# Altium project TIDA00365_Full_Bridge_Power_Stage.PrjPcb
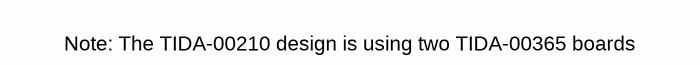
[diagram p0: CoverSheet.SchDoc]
CopyrightYear: 2016; EVM_Orderable: N/A; PCB_Layout: V.Pizzolante; PCB_Rev: E1; PRJ_Customer: Public Release; PRJ_Engineer: V.Pizzolante; PRJ_Number: TIDA-00365; PRJ_Title: Full_Bridge_Power_Stage; SCH_Rev: E1; TechSupport: http://www.ti.com/support; TID: TIDA-00365
6 sheets, 182 parts. Net scope: global (net labels, ports and power ports of the same name join across sheets).
Board file: TIDA00365.PcbDoc
Sheets:
  CoverSheet.SchDoc
  Protections.SchDoc
  Power Supply.SchDoc
  Full Bridge.SchDoc
  Interfaces.SchDoc
  TIDA00365_Screws.SchDoc

## Sheet CoverSheet.SchDoc
size 431 x 279 mm; Date: Not shown in title block; ApprovedBy: Not shown in title block; CheckedBy: Not shown in title block; Author: Not shown in title block; CompanyName: Not shown in title block; Engineer: Not shown in title block; Organization: Not shown in title block; Address1: Not shown in title block; Address2: Not shown in title block; Address3: Not shown in title block; Address4: Not shown in title block; DocumentNumber: 1; Revision: Use project parameter SCH_Rev; SheetNumber: 1; SheetTotal: 3

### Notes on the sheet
- Note: The TIDA-00210 design is using two TIDA-00365 boards

## Sheet Protections.SchDoc
size 431 x 279 mm; Date: Not shown in title block; ApprovedBy: Not shown in title block; CheckedBy: Not shown in title block; Author: Not shown in title block; CompanyName: Not shown in title block; Engineer: Not shown in title block; Organization: Not shown in title block; Address1: Not shown in title block; Address2: Not shown in title block; Address3: Not shown in title block; Address4: Not shown in title block; DocumentNumber: 1; Revision: Use project parameter SCH_Rev; SheetNumber: 2; SheetTotal: 3
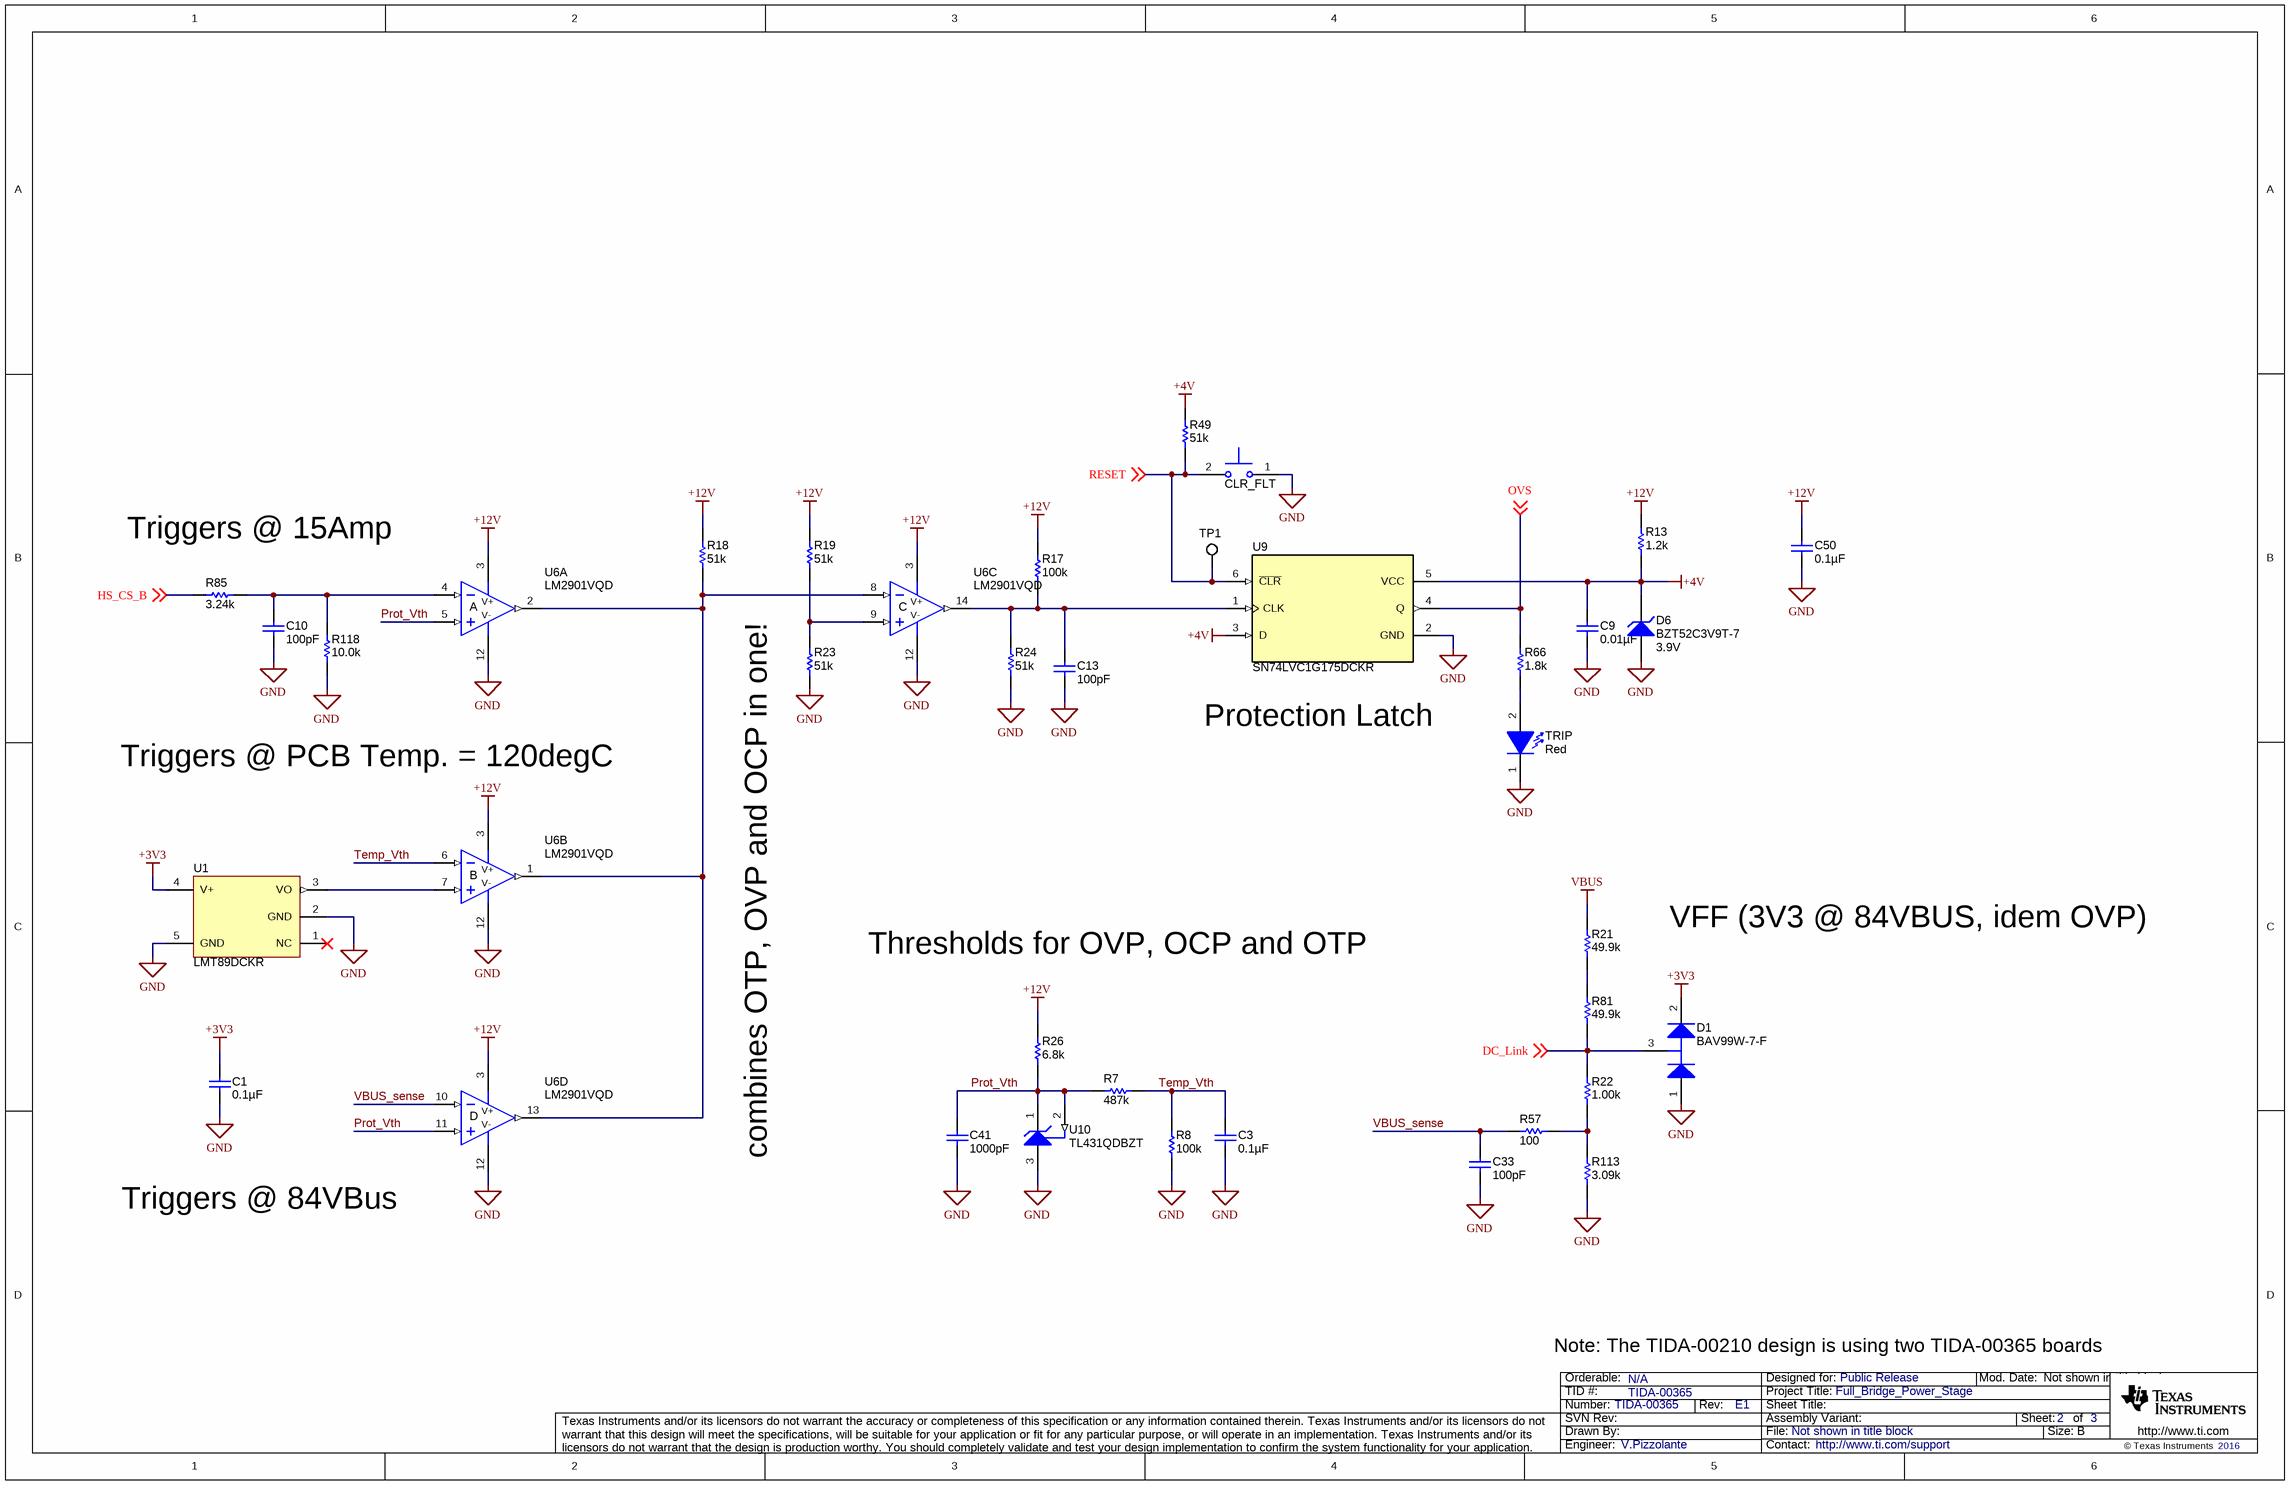
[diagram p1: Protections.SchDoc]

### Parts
C1  ValueDisplayed: 0.1µF  [0402]  (hidden comment: C1005X7R1E104M050BB)
C3  ValueDisplayed: 0.1µF  [0402]  (hidden comment: 885012105016)
C9  ValueDisplayed: 0.01µF  [0402]  (hidden comment: 885012205031)
C10  ValueDisplayed: 100pF  [0402]  (hidden comment: CC0402KRX7R9BB101)
C13  ValueDisplayed: 100pF  [0402]  (hidden comment: CC0402KRX7R9BB101)
C33  ValueDisplayed: 100pF  [0402]  (hidden comment: CC0402KRX7R9BB101)
C41  ValueDisplayed: 1000pF  [0402]  (hidden comment: 885012205044)
C50  ValueDisplayed: 0.1µF  [0402]  (hidden comment: C1005X7R1E104M050BB)
CLR_FLT  TL1015AF160QG  [SW_TL1015AF160QG]  (value not drawn)
D1  BAV99W-7-F  [SOT-323]
D6  BZT52C3V9T-7  value 3.9V  [SOD-523]
R7  ValueDisplayed: 487k  [0402]  (hidden comment: CRCW0402487KFKED)
R8  ValueDisplayed: 100k  [0402]  (hidden comment: CRCW0402100KFKED)
R13  ValueDisplayed: 1.2k  [0402]  (hidden comment: CRCW04021K20JNED)
R17  ValueDisplayed: 100k  [0402]  (hidden comment: CRCW0402100KJNED)
R18  ValueDisplayed: 51k  [0402]  (hidden comment: CRCW040251K0JNED)
R19  ValueDisplayed: 51k  [0402]  (hidden comment: CRCW040251K0JNED)
R21  ValueDisplayed: 49.9k  [0402]  (hidden comment: CRCW040249K9FKED)
R22  ValueDisplayed: 1.00k  [0402]  (hidden comment: CRCW04021K00FKED)
R23  ValueDisplayed: 51k  [0402]  (hidden comment: CRCW040251K0JNED)
R24  ValueDisplayed: 51k  [0402]  (hidden comment: CRCW040251K0JNED)
R26  ValueDisplayed: 6.8k  [0402]  (hidden comment: CRCW04026K80JNED)
R49  ValueDisplayed: 51k  [0402]  (hidden comment: CRCW040251K0JNED)
R57  ValueDisplayed: 100  [0402]  (hidden comment: CRCW0402100RJNED)
R66  ValueDisplayed: 1.8k  [0402]  (hidden comment: CRCW04021K80JNED)
R81  ValueDisplayed: 49.9k  [0402]  (hidden comment: CRCW040249K9FKED)
R85  ValueDisplayed: 3.24k  [0402]  (hidden comment: CRCW04023K24FKED)
R113  ValueDisplayed: 3.09k  [0402]  (hidden comment: CRCW04023K09FKED)
R118  ValueDisplayed: 10.0k  [0402]  (hidden comment: CRCW040210K0FKED)
TP1  5002  [Keystone5002]  (value not drawn)
TRIP  value Red  [WL-SMCW_RED]  (hidden comment: 150060RS75000)
U1  LMT89DCKR  [DCK0005A_N]
U6  LM2901VQD  [D0014A_N]  (parts A,B,C,D of 4)
U9  SN74LVC1G175DCKR  [DCK0006A_N]
U10  TL431QDBZT  [DBZ0003A_N]

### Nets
+3V3: C1.1 D1.2(K) U1.4(V+)
+4V: C9.1 D6.1(K) R13.1 R49.2 U9.3(D) U9.5(VCC)
+12V: C50.1 R13.2 R17.2 R18.1 R19.1 R26.2 U6.3(V+)
GND: C1.2 C3.2 C9.2 C10.2 C13.2 C33.2 C41.2 C50.2 CLR_FLT.1 D1.1(A) D6.2(A) R8.1 R23.2 R24.1 R113.1 R118.1 TRIP.1(K) U1.2(GND) U1.5(GND) U6.12(V-) U9.2(GND) U10.3(ANODE)
VBUS: R21.2
DC_Link: D1.3(C) R22.2 R81.1 ; off-sheet DC_Link
HS_CS_B: R85.1 ; off-sheet HS_CS_B  [project net BOUT_2]
OVS: R66.1 U9.4(Q) ; off-sheet OVS
Prot_Vth: C41.1 R7.2 R26.1 U6.5(+IN1) U6.11(+IN4) U10.1(CATHODE) U10.2(REF)
RESET: CLR_FLT.2 R49.1 TP1.1 U9.6(~{CLR}) ; off-sheet RESET
Temp_Vth: C3.1 R7.1 R8.2 U6.6(-IN2)
VBUS_sense: C33.1 R57.1 U6.10(-IN4)
NetC10_1: C10.1 R85.2 R118.2 U6.4(-IN1)
NetC13_1: C13.1 R17.1 R24.2 U6.14(OUT3) U9.1(CLK)
NetR18_2: R18.2 U6.1(OUT2) U6.2(OUT1) U6.8(-IN3) U6.13(OUT4)
NetR19_2: R19.2 R23.1 U6.9(+IN3)
NetR21_1: R21.1 R81.2
NetR22_1: R22.1 R57.2 R113.2
NetR66_2: R66.2 TRIP.2(A)
NetU1_3: U1.3(VO) U6.7(+IN2)

Not connected (* = marked no-connect by the designer): U1 1(NC)*

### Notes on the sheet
- Triggers @ 15Amp
- Triggers @ PCB Temp. = 120degC
- Protection Latch
- (near R23) combines OTP, OVP and OCP in one!
- Thresholds for OVP, OCP and OTP
- VFF (3V3 @ 84VBUS, idem OVP)
- Triggers @ 84VBus
- Note: The TIDA-00210 design is using two TIDA-00365 boards

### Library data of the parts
C1 C50 = C1005X7R1E104M050BB: CAP, CERM, 0.1 µF, 25 V, +/- 20%, X7R, 0402; Manufacturer: TDK; Polarized: N; CompType: Capacitor; Value: 0.1uF; U/M: EA; Cap_F: 0.0000001; Tolerance_%: 20; Value1: Unknown; VDC_V: 25; Value2: 25V; TaMin_C: -55; TaMax_C: 125; AEC Category: Q200
C3 = 885012105016: CAP, CERM, 0.1 µF, 16 V, +/- 20%, X5R, 0402; Manufacturer: Wurth Elektronik; Polarized: N; CompType: Capacitor; Value: 0.1uF; U/M: EA; Cap_F: 0.0000001; Tolerance_%: 20; Value1: Unknown; VDC_V: 16; Value2: 16V; TaMin_C: -55; TaMax_C: 85; AEC Category: Q200
C9 = 885012205031: CAP, CERM, 0.01 µF, 16 V, +/- 10%, X7R, 0402; Manufacturer: Wurth Elektronik; Polarized: N; CompType: Capacitor; Value: 0.01uF; U/M: EA; Cap_F: 0.00000001; Tolerance_%: 10; Value1: Unknown; VDC_V: 16; Value2: 16V; TaMin_C: -55; TaMax_C: 125; AEC Category: Q200
C10 C13 C33 = CC0402KRX7R9BB101: CAP, CERM, 100 pF, 50 V, +/- 10%, X7R, 0402; Manufacturer: Yageo America; Polarized: N; CompType: Capacitor; Value: 100pF; U/M: EA; Cap_F: 0.0000000001; Tolerance_%: 10; Value1: Unknown; VDC_V: 50; Value2: 50V; TaMin_C: -55; TaMax_C: 125; AEC Category: Q200
C41 = 885012205044: CAP, CERM, 1000 pF, 25 V, +/- 10%, X7R, 0402; Manufacturer: Wurth Elektronik; Polarized: N; CompType: Capacitor; Value: 1000pF; U/M: EA; Cap_F: 0.000000001; Tolerance_%: 10; Value1: Unknown; VDC_V: 25; Value2: 25V; TaMin_C: -55; TaMax_C: 125; AEC Category: Q200
CLR_FLT = TL1015AF160QG: Switch, Tactile, SPST-NO, 0.05A, 12V, SMT; Manufacturer: E-Switch; SymbolCreator: a0412235; VDC_V: 12; SwitchFunction: Off-Mom; PositionCount: 1; CurrentRating_mA: 50
D1 = BAV99W-7-F: Diode, Switching, 75 V, 0.15 A, SOT-323; Manufacturer: Diodes Inc.; U/M: EA; Vf_V: 1.25; Value: 75V; Value1: 0.15A; Value2: 1.25V; Io_A: 0.15; Vr_V: 75; TJmax_C: 150; AEC Category: Q101
D6 = BZT52C3V9T-7: Diode, Zener, 3.9 V, 300 mW, SOD-523; Manufacturer: Diodes Inc.; SymbolCreator: a0412235; U/M: EA; Power_W: 0.3; Vz_V: 3.9; Value1: 0.3W; RJA_CperW: 417; AEC Category: Q101
R7 = CRCW0402487KFKED: RES, 487 k, 1%, 0.063 W, 0402; Manufacturer: Vishay-Dale; CompType: Resistor; Value: 487k; Res_ohm: 487000; Tolerance_%: 1; Power_W: 0.063; Value2: 0.063W; VDC_V: 50; TempCo: 100 ppm/C; EIA_Code: E96; U/M: EA; AEC Category: Q200
R8 = CRCW0402100KFKED: RES, 100 k, 1%, 0.063 W, 0402; Manufacturer: Vishay-Dale; CompType: Resistor; Value: 100k; Res_ohm: 100000; Tolerance_%: 1; Power_W: 0.063; Value2: 0.063W; VDC_V: 50; TempCo: 100 ppm/C; EIA_Code: E96; U/M: EA; AEC Category: Q200
R13 = CRCW04021K20JNED: RES, 1.2 k, 5%, 0.063 W, 0402; Manufacturer: Vishay-Dale; CompType: Resistor; Value: 1.2k; Res_ohm: 1200; Value_Code: 1k20; Tolerance_%: 5; Power_W: 0.063; Value2: 0.063W; VDC_V: 50; TempCo: 200 ppm/C; EIA_Code: E24; U/M: EA; AEC Category: Q200
R17 = CRCW0402100KJNED: RES, 100 k, 5%, 0.063 W, 0402; Manufacturer: Vishay-Dale; CompType: Resistor; Value: 100k; Res_ohm: 100000; Tolerance_%: 5; Power_W: 0.063; Value2: 0.063W; VDC_V: 50; TempCo: 200 ppm/C; EIA_Code: E24; U/M: EA; AEC Category: Q200
R18 R19 R23 R24 R49 = CRCW040251K0JNED: RES, 51 k, 5%, 0.063 W, 0402; Manufacturer: Vishay-Dale; CompType: Resistor; Value: 51k; Res_ohm: 51000; Value_Code: 51k0; Tolerance_%: 5; Power_W: 0.063; Value2: 0.063W; VDC_V: 50; TempCo: 200 ppm/C; EIA_Code: E24; U/M: EA; AEC Category: Q200
R21 R81 = CRCW040249K9FKED: RES, 49.9 k, 1%, 0.063 W, 0402; Manufacturer: Vishay-Dale; CompType: Resistor; Value: 49.9k; Res_ohm: 49900; Value_Code: 49k9; Tolerance_%: 1; Power_W: 0.063; Value2: 0.063W; VDC_V: 50; TempCo: 100 ppm/C; EIA_Code: E96; U/M: EA; AEC Category: Q200
R22 = CRCW04021K00FKED: RES, 1.00 k, 1%, 0.063 W, 0402; Manufacturer: Vishay-Dale; CompType: Resistor; Value: 1.00k; Res_ohm: 1000; Value_Code: 1k00; Tolerance_%: 1; Power_W: 0.063; Value2: 0.063W; VDC_V: 50; TempCo: 100 ppm/C; EIA_Code: E96; U/M: EA; AEC Category: Q200
R26 = CRCW04026K80JNED: RES, 6.8 k, 5%, 0.063 W, 0402; Manufacturer: Vishay-Dale; CompType: Resistor; Value: 6.8k; Res_ohm: 6800; Value_Code: 6k80; Tolerance_%: 5; Power_W: 0.063; Value2: 0.063W; VDC_V: 50; TempCo: 200 ppm/C; EIA_Code: E24; U/M: EA; AEC Category: Q200
R57 = CRCW0402100RJNED: RES, 100, 5%, 0.063 W, 0402; Manufacturer: Vishay-Dale; CompType: Resistor; Value: 100; Value_Code: 100R; Tolerance_%: 5; Power_W: 0.063; Value2: 0.063W; VDC_V: 50; TempCo: 200 ppm/C; EIA_Code: E24; U/M: EA; AEC Category: Q200
R66 = CRCW04021K80JNED: RES, 1.8 k, 5%, 0.063 W, 0402; Manufacturer: Vishay-Dale; CompType: Resistor; Value: 1.8k; Res_ohm: 1800; Value_Code: 1k80; Tolerance_%: 5; Power_W: 0.063; Value2: 0.063W; VDC_V: 50; TempCo: 200 ppm/C; EIA_Code: E24; U/M: EA; AEC Category: Q200
R85 = CRCW04023K24FKED: RES, 3.24 k, 1%, 0.063 W, 0402; Manufacturer: Vishay-Dale; CompType: Resistor; Value: 3.24k; Res_ohm: 3240; Value_Code: 3k24; Tolerance_%: 1; Power_W: 0.063; Value2: 0.063W; VDC_V: 50; TempCo: 100 ppm/C; EIA_Code: E96; U/M: EA; AEC Category: Q200
R113 = CRCW04023K09FKED: RES, 3.09 k, 1%, 0.063 W, 0402; Manufacturer: Vishay-Dale; CompType: Resistor; Value: 3.09k; Res_ohm: 3090; Value_Code: 3k09; Tolerance_%: 1; Power_W: 0.063; Value2: 0.063W; VDC_V: 50; TempCo: 100 ppm/C; EIA_Code: E96; U/M: EA; AEC Category: Q200
R118 = CRCW040210K0FKED: RES, 10.0 k, 1%, 0.063 W, 0402; Manufacturer: Vishay-Dale; CompType: Resistor; Value: 10.0k; Res_ohm: 10000; Value_Code: 10k0; Tolerance_%: 1; Power_W: 0.063; Value2: 0.063W; VDC_V: 50; TempCo: 100 ppm/C; EIA_Code: E96; U/M: EA; AEC Category: Q200
TP1 = 5002: Test Point, Miniature, White, TH; Manufacturer: Keystone; CompType: Test Point Loop; ContactFinish: Silver
TRIP = 150060RS75000: LED, Red, SMD; Manufacturer: Wurth Elektronik; Vf_V: 2; Value2: 2V; Io_A: 0.03; Vr_V: 5; Tjmax_C: 85; Power_TotalModule: 0.072; Value1: 0.072W; Angle: 140; U/M: EA
U1 = LMT89DCKR: 2.4V, 10μA, SC70, DSBGA Temperature Sensor, DCK0005A; Alternate PartNumber: LMT89DCKT; Manufacturer: Texas Instruments; SymbolCreator: a0412235; CompType: IC; U/M: EA
U6 = LM2901VQD: Quad Comparator, D0014A; Manufacturer: Texas Instruments; SymbolCreator: Altium; CompType: OpAmp IC
U9 = SN74LVC1G175DCKR: SINGLE D-TYPE FLIP-FLOP WITH ASYNCHRONOUS CLEAR, DCK0006A; Alternate PartNumber: SN74LVC1G175DCKT; Manufacturer: Texas Instruments; SymbolCreator: Altium; CompType: IC; U/M: EA
U10 = TL431QDBZT: Adjustable Precision Shunt Regulator, 34 ppm / degC, 100 mA, -40 to 125 degC, 3-pin SOT-23 (DBZ), Green (RoHS & no Sb/Br); Manufacturer: Texas Instruments; Alternate PartNumber: Equivalent; Initial Accuracy @ 25/deg C(%): 2; Iout/Iz(Max)(mA): 100; Min Iz for Regulation(uA): 600; Rating: Military; SubFamily: Shunt Voltage Reference; Temp Coeff(Max)(ppm/ degree C): 92; Temp Coeff(Typ)(ppm/ degree C): 34; VO Adj(Max)(V): 36; VO Adj(Min)(V): 2.495

## Sheet Power Supply.SchDoc
size 431 x 279 mm; Date: Not shown in title block; ApprovedBy: Not shown in title block; CheckedBy: Not shown in title block; Author: Not shown in title block; CompanyName: Not shown in title block; Engineer: Not shown in title block; Organization: Not shown in title block; Address1: Not shown in title block; Address2: Not shown in title block; Address3: Not shown in title block; Address4: Not shown in title block; DocumentNumber: 1; Revision: Use project parameter SCH_Rev; SheetNumber: 2; SheetTotal: 3
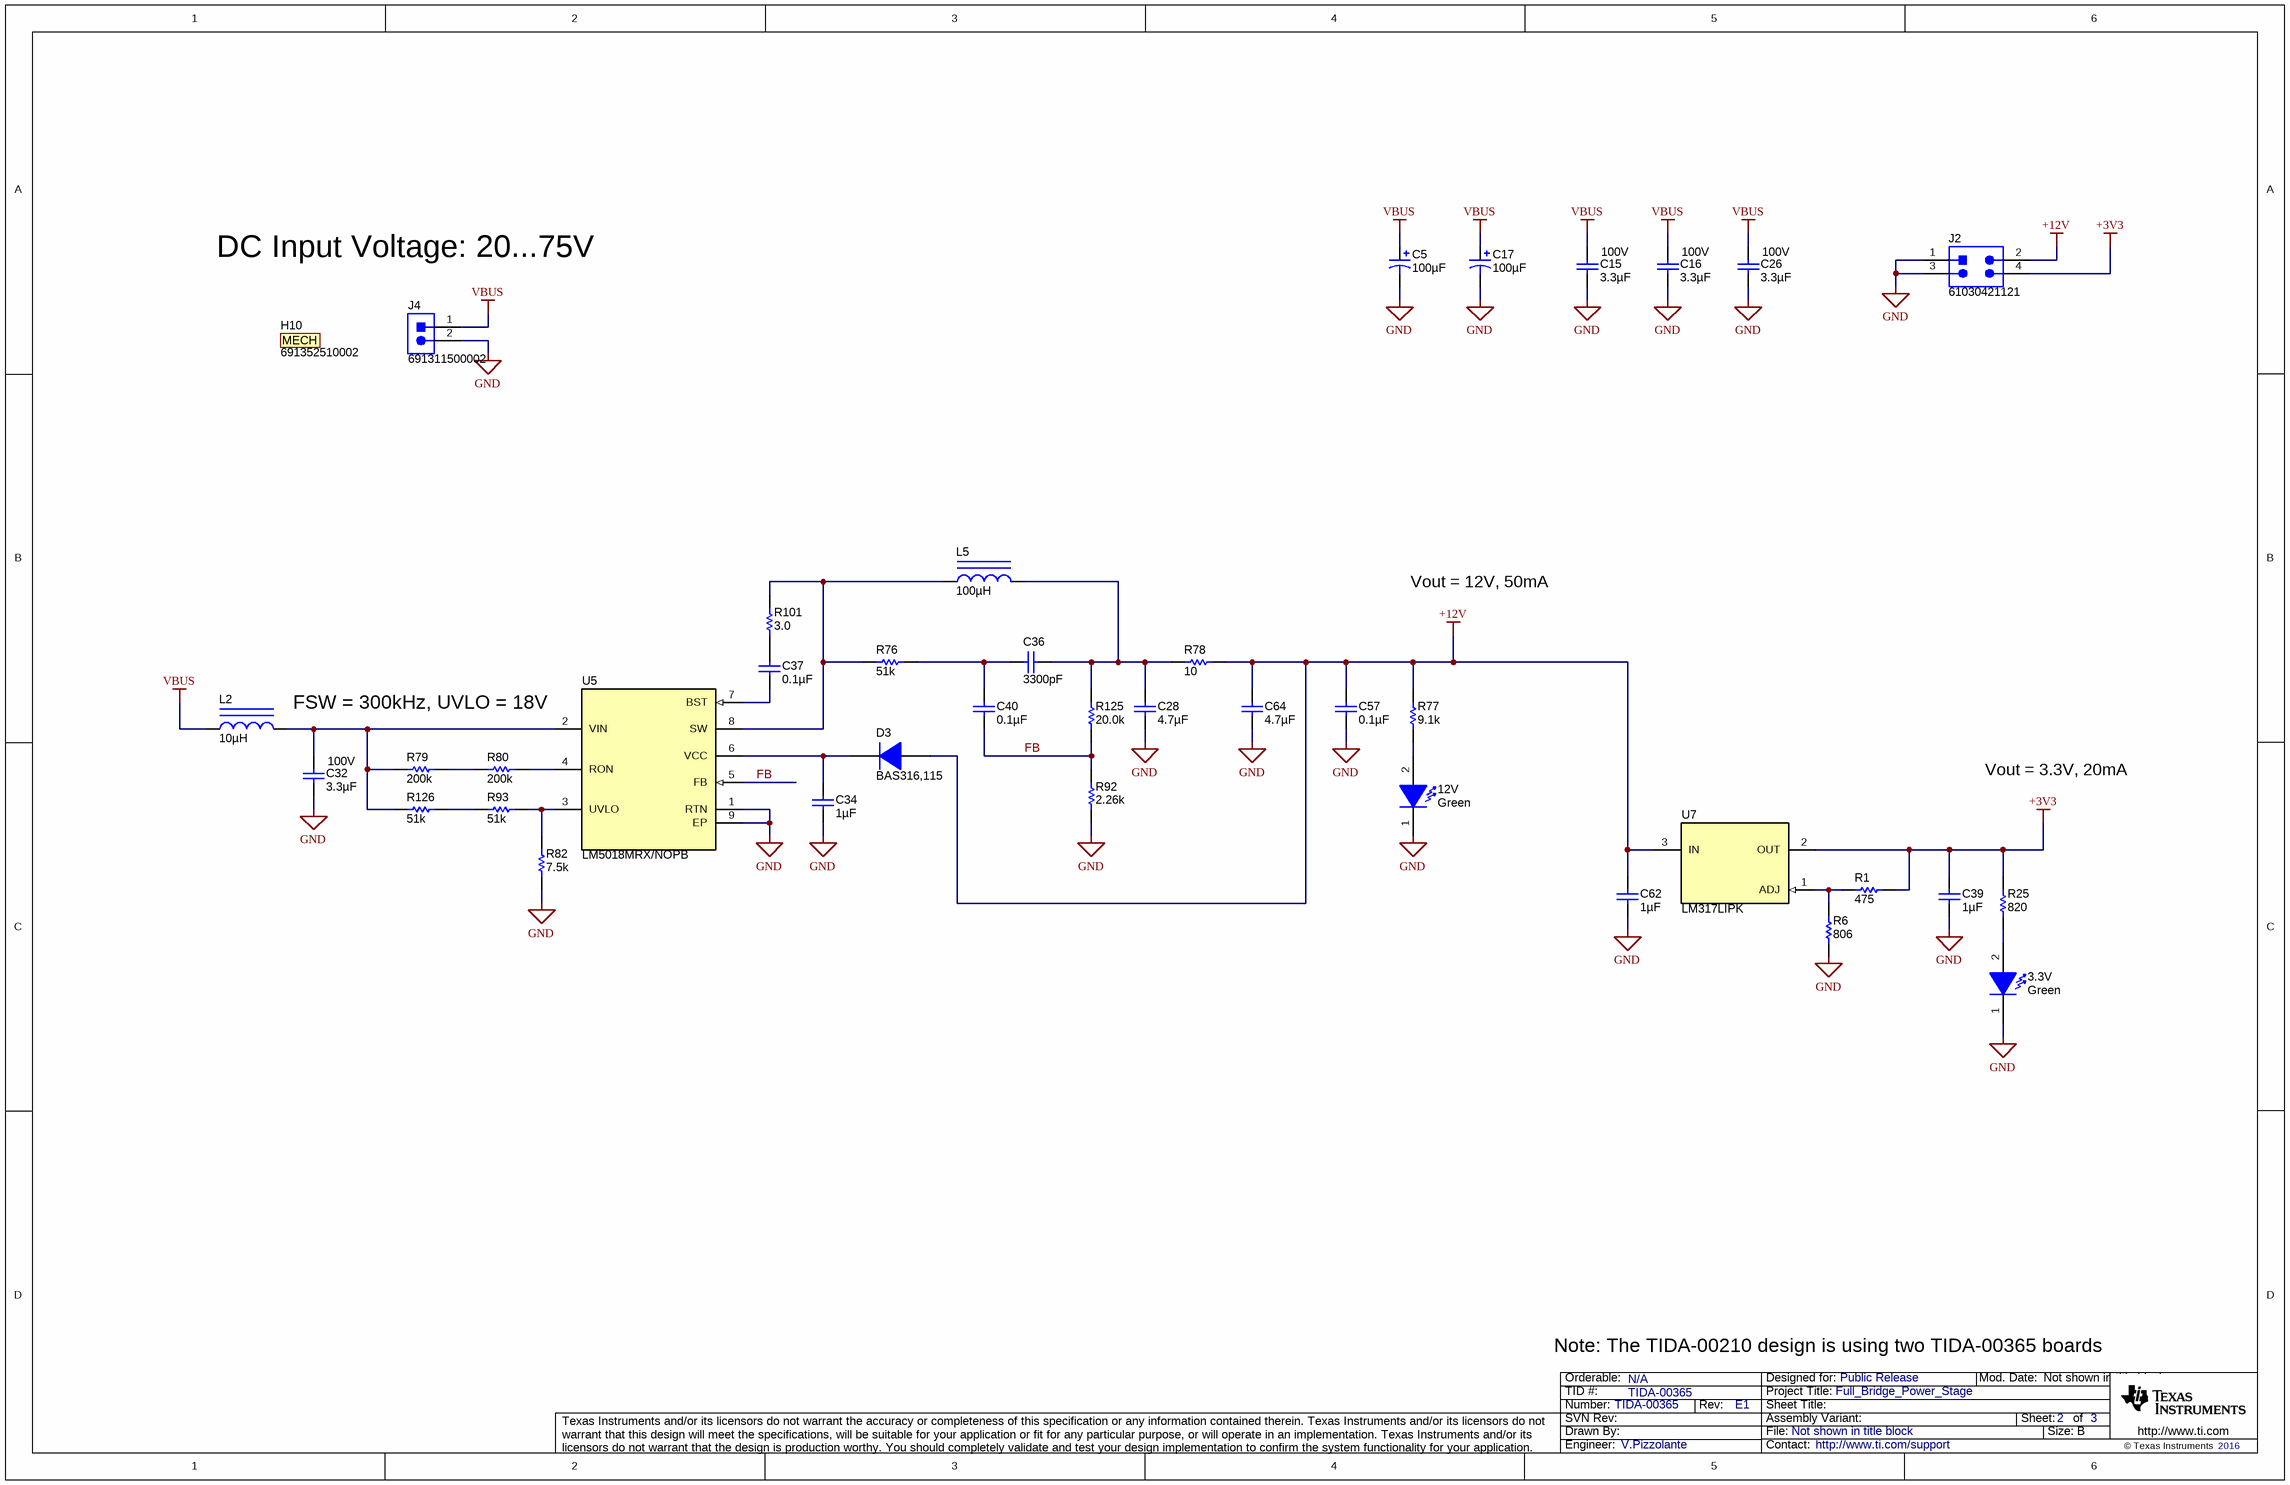
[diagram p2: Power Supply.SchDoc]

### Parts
3.3V  value Green  [WL-SMCW_GREEN]  (hidden comment: 150060GS75000)
12V  value Green  [WL-SMCW_GREEN]  (hidden comment: 150060GS75000)
C5  ValueDisplayed: 100µF  [WCAP-ATUL_1000x2500]  (hidden comment: 860040875005)
C15  ValueDisplayed: 3.3µF  Value2: 100V  [1206_190]  (hidden comment: C3216X7S2A335M160AB)
C16  ValueDisplayed: 3.3µF  Value2: 100V  [1206_190]  (hidden comment: C3216X7S2A335M160AB)
C17  ValueDisplayed: 100µF  [WCAP-ATUL_1000x2500]  (hidden comment: 860040875005)
C26  ValueDisplayed: 3.3µF  Value2: 100V  [1206_190]  (hidden comment: C3216X7S2A335M160AB)
C28  ValueDisplayed: 4.7µF  [0603]  (hidden comment: GRM188R61E475KE11D)
C32  ValueDisplayed: 3.3µF  Value2: 100V  [1206_190]  (hidden comment: C3216X7S2A335M160AB)
C34  ValueDisplayed: 1µF  [0603]  (hidden comment: C1608X5R1C105K)
C36  ValueDisplayed: 3300pF  [0603]  (hidden comment: GRM188R72A332KA01D)
C37  ValueDisplayed: 0.1µF  [0603]  (hidden comment: GRM188R72A104KA35D)
C39  ValueDisplayed: 1µF  [0603]  (hidden comment: C1608X5R1C105K)
C40  ValueDisplayed: 0.1µF  [0402]  (hidden comment: C1005X7R1E104M050BB)
C57  ValueDisplayed: 0.1µF  [0402]  (hidden comment: C1005X7R1E104M050BB)
C62  ValueDisplayed: 1µF  [0603]  (hidden comment: C1608X5R1C105K)
C64  ValueDisplayed: 4.7µF  [0603]  (hidden comment: GRM188R61E475KE11D)
D3  BAS316,115  [sod-323]
H10  691352510002  (mechanical)
J2  61030421121  [Wurth_61030421121]
J4  691311500002  [Wurth_691311500002]
L2  ValueDisplayed: 10µH  [WE-PMI_1008]  (hidden comment: 74479887310)
L5  ValueDisplayed: 100µH  [WE-LQS_4012]  (hidden comment: 74404041101)
R1  ValueDisplayed: 475  [0402]  (hidden comment: CRCW0402475RFKED)
R6  ValueDisplayed: 806  [0402]  (hidden comment: CRCW0402806RFKED)
R25  ValueDisplayed: 820  [0402]  (hidden comment: CRCW0402820RJNED)
R76  ValueDisplayed: 51k  [0402]  (hidden comment: CRCW040251K0JNED)
R77  ValueDisplayed: 9.1k  [0402]  (hidden comment: CRCW04029K10JNED)
R78  ValueDisplayed: 10  [0603]  (hidden comment: CRCW060310R0JNEA)
R79  ValueDisplayed: 200k  [0402]  (hidden comment: CRCW0402200KJNED)
R80  ValueDisplayed: 200k  [0402]  (hidden comment: CRCW0402200KJNED)
R82  ValueDisplayed: 7.5k  [0402]  (hidden comment: CRCW04027K50JNED)
R92  ValueDisplayed: 2.26k  [0402]  (hidden comment: CRCW04022K26FKED)
R93  ValueDisplayed: 51k  [0402]  (hidden comment: CRCW040251K0JNED)
R101  ValueDisplayed: 3.0  [0402]  (hidden comment: CRCW04023R00JNED)
R125  ValueDisplayed: 20.0k  [0402]  (hidden comment: CRCW040220K0FKED)
R126  ValueDisplayed: 51k  [0402]  (hidden comment: CRCW040251K0JNED)
U5  LM5018MRX/NOPB  [DDA0008B_N]
U7  LM317LIPK  [PK0003A_N]

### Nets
+3V3: C39.1 J2.4 R1.2 R25.2 U7.2(OUT)
+12V: C57.1 C62.1 C64.1 D3.2(A) J2.2 R77.2 R78.2 U7.3(IN)
GND: 3.3V.1(K) 12V.1(K) C5.2(-) C15.2 C16.2 C17.2(-) C26.2 C28.2 C32.2 C34.2 C39.2 C57.2 C62.2 C64.2 J2.1 J2.3 J4.2 R6.1 R82.1 R92.1 U5.1(RTN) U5.9(EP)
VBUS: C5.1(+) C15.1 C16.1 C17.1(+) C26.1 J4.1 L2.1
FB: C40.2 R92.2 R125.1 U5.5(FB)
Net3.3V_2: 3.3V.2(A) R25.1
Net12V_2: 12V.2(A) R77.1
NetC28_1: C28.1 C36.1 L5.2 R78.1 R125.2
NetC32_1: C32.1 L2.2 R79.1 R126.1 U5.2(VIN)
NetC34_1: C34.1 D3.1(K) U5.6(VCC)
NetC36_2: C36.2 C40.1 R76.2
NetC37_1: C37.1 U5.7(BST)
NetC37_2: C37.2 R101.1
NetL5_1: L5.1 R76.1 R101.2 U5.8(SW)
NetR1_1: R1.1 R6.2 U7.1(ADJ)
NetR79_2: R79.2 R80.1
NetR80_2: R80.2 U5.4(RON)
NetR82_2: R82.2 R93.2 U5.3(UVLO)
NetR93_1: R93.1 R126.2

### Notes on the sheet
- DC Input Voltage: 20...75V
- Vout = 12V, 50mA
- FSW = 300kHz, UVLO = 18V
- Vout = 3.3V, 20mA
- Note: The TIDA-00210 design is using two TIDA-00365 boards

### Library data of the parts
3.3V 12V = 150060GS75000: LED, Green, SMD; Manufacturer: Wurth Elektronik; Vf_V: 3.2; Value2: 3.2V; Io_A: 0.02; Tjmax_C: 85; Value1: W; Angle: 140; U/M: EA
C5 C17 = 860040875005: CAP, AL, 100 µF, 100 V, +/- 20%, 0.2 ohm, TH; Manufacturer: Wurth Elektronik; Polarized: Y; CompType: Capacitor; Value: 100uF; U/M: EA; Cap_F: 0.0001; Tolerance_%: 20; Value1: 0.2 ohm; VDC_V: 100; Value2: 100V; ESR_ohm: 0.2; IRMS_A: 0.8; TaMin_C: -40; TaMax_C: 105; Cap_Case: 10x25mm; AEC Category: Q200; AEC Qualified: N
C15 C16 C26 C32 = C3216X7S2A335M160AB: CAP, CERM, 3.3 µF, 100 V, +/- 20%, X7S, 1206_190; Manufacturer: TDK; Polarized: N; CompType: Capacitor; Value: 3.3uF; U/M: EA; Cap_F: 0.0000033; Tolerance_%: 20; Value1: Unknown; VDC_V: 100; TaMin_C: -55; TaMax_C: 125; Cap_Case: 1206; AEC Category: Q200
C28 C64 = GRM188R61E475KE11D: CAP, CERM, 4.7 µF, 25 V, +/- 10%, X5R, 0603; Manufacturer: MuRata; Polarized: N; CompType: Capacitor; Value: 4.7uF; U/M: EA; Cap_F: 0.0000047; Tolerance_%: 10; Value1: Unknown; VDC_V: 25; Value2: 25V; TaMin_C: -55; TaMax_C: 85; AEC Category: Q200
C34 C39 C62 = C1608X5R1C105K: CAP, CERM, 1 µF, 16 V, +/- 10%, X5R, 0603; Manufacturer: TDK; Polarized: N; CompType: Capacitor; Value: 1uF; U/M: EA; Cap_F: 0.000001; Tolerance_%: 10; ESR_ohm: 0.0057; Value1: 0.0057 ohm; VDC_V: 16; Value2: 16V; TaMin_C: -55; TaMax_C: 85; AEC Category: Q200
C36 = GRM188R72A332KA01D: CAP, CERM, 3300 pF, 100 V, +/- 10%, X7R, 0603; Manufacturer: MuRata; Polarized: N; CompType: Capacitor; Value: 3300pF; U/M: EA; Cap_F: 0.0000000033; Tolerance_%: 10; Value1: Unknown; VDC_V: 100; Value2: 100V; TaMin_C: -55; TaMax_C: 125; AEC Category: Q200
C37 = GRM188R72A104KA35D: CAP, CERM, 0.1 µF, 100 V, +/- 10%, X7R, 0603; Manufacturer: MuRata; Polarized: N; CompType: Capacitor; Value: 0.1uF; U/M: EA; Cap_F: 0.0000001; Tolerance_%: 10; Value1: Unknown; VDC_V: 100; Value2: 100V; TaMin_C: -55; TaMax_C: 125; AEC Category: Q200
C40 C57 = C1005X7R1E104M050BB: as C1 on sheet Protections
D3 = BAS316,115: Diode, Ultrafast, 100 V, 0.25 A, SOD-323; Manufacturer: NXP Semiconductor; U/M: EA; Vf_V: 1.4; Value: 100V; Value1: 0.25A; Value2: 1.4V; Io_A: 0.25; Vr_V: 100; TJmax_C: 150; AEC Category: Q101
H10 = 691352510002: TERM BLOCK PLUG 2POS 5.08MM; Manufacturer: Wurth Elektronik; SymbolCreator: codlsc
J2 = 61030421121: Header, 2.54mm, 2x2, Gold, SMT; Manufacturer: Wurth Elektronik; SymbolCreator: a0412235; Pitch_mm: 2.54; Gender: Male; Shrouded: N; Row_Count: 2; Current_A: 3; Voltage_V: 250
J4 = 691311500002: Header (Shrouded), 5.08mm, 2x1, Tin, TH; Manufacturer: Wurth Elektronik; SymbolCreator: a0412235; Pitch_mm: 5.08; Gender: Male; Shrouded: Y; Row_Count: 1; Current_A: 20; Voltage_V: 300
L2 = 74479887310: Inductor, Shielded Drum Core, Metal Composite, 10 µH, 0.35 A, 0.7 ohm, SMD; Manufacturer: Wurth Elektronik; Value: 10uH; Ind_H: 10.0E-6; Imax_A: 0.35; Irms: 0.5A @ 40C rise; Isat: 0.35A @ 30% inductance drop; DCR_ohm: 0.7; Value1: 0.7 ohm; Value2: 0.35A; AEC Category: Q200
L5 = 74404041101: Inductor, Wirewound, Ferrite, 100 µH, 0.35 A, 1.697 ohm, SMD; Manufacturer: Wurth Elektronik; Value: 100uH; Ind_H: 100.0E-6; Imax_A: 0.35; Irms: 0.43A @ 40C rise; Isat: 0.35A @ 30% inductance drop; DCR_ohm: 1.697; Value2: 0.35A; AEC Category: Q200; AEC Qualified: N
R1 = CRCW0402475RFKED: RES, 475, 1%, 0.063 W, 0402; Manufacturer: Vishay-Dale; CompType: Resistor; Value: 475; Value_Code: 475R; Tolerance_%: 1; Power_W: 0.063; Value2: 0.063W; VDC_V: 50; TempCo: 100 ppm/C; EIA_Code: E96; U/M: EA; AEC Category: Q200
R6 = CRCW0402806RFKED: RES, 806, 1%, 0.063 W, 0402; Manufacturer: Vishay-Dale; CompType: Resistor; Value: 806; Value_Code: 806R; Tolerance_%: 1; Power_W: 0.063; Value2: 0.063W; VDC_V: 50; TempCo: 100 ppm/C; EIA_Code: E96; U/M: EA; AEC Category: Q200
R25 = CRCW0402820RJNED: RES, 820, 5%, 0.063 W, 0402; Manufacturer: Vishay-Dale; CompType: Resistor; Value: 820; Value_Code: 820R; Tolerance_%: 5; Power_W: 0.063; Value2: 0.063W; VDC_V: 50; TempCo: 200 ppm/C; EIA_Code: E24; U/M: EA; AEC Category: Q200
R76 R93 R126 = CRCW040251K0JNED: as R18 on sheet Protections
R77 = CRCW04029K10JNED: RES, 9.1 k, 5%, 0.063 W, 0402; Manufacturer: Vishay-Dale; CompType: Resistor; Value: 9.1k; Res_ohm: 9100; Value_Code: 9k10; Tolerance_%: 5; Power_W: 0.063; Value2: 0.063W; VDC_V: 50; TempCo: 200 ppm/C; EIA_Code: E24; U/M: EA; AEC Category: Q200
R78 = CRCW060310R0JNEA: RES, 10, 5%, 0.1 W, 0603; Manufacturer: Vishay-Dale; CompType: Resistor; Value: 10; Value_Code: 10R0; Tolerance_%: 5; Power_W: 0.1; Value2: 0.1W; VDC_V: 75; TempCo: 200 ppm/C; EIA_Code: E24; U/M: EA; AEC Category: Q200
R79 R80 = CRCW0402200KJNED: RES, 200 k, 5%, 0.063 W, 0402; Manufacturer: Vishay-Dale; CompType: Resistor; Value: 200k; Res_ohm: 200000; Tolerance_%: 5; Power_W: 0.063; Value2: 0.063W; VDC_V: 50; TempCo: 200 ppm/C; EIA_Code: E24; U/M: EA; AEC Category: Q200
R82 = CRCW04027K50JNED: RES, 7.5 k, 5%, 0.063 W, 0402; Manufacturer: Vishay-Dale; CompType: Resistor; Value: 7.5k; Res_ohm: 7500; Value_Code: 7k50; Tolerance_%: 5; Power_W: 0.063; Value2: 0.063W; VDC_V: 50; TempCo: 200 ppm/C; EIA_Code: E24; U/M: EA; AEC Category: Q200
R92 = CRCW04022K26FKED: RES, 2.26 k, 1%, 0.063 W, 0402; Manufacturer: Vishay-Dale; CompType: Resistor; Value: 2.26k; Res_ohm: 2260; Value_Code: 2k26; Tolerance_%: 1; Power_W: 0.063; Value2: 0.063W; VDC_V: 50; TempCo: 100 ppm/C; EIA_Code: E96; U/M: EA; AEC Category: Q200
R101 = CRCW04023R00JNED: RES, 3.0, 5%, 0.063 W, 0402; Manufacturer: Vishay-Dale; CompType: Resistor; Value: 3.0; Res_ohm: 3; Value_Code: 3R00; Tolerance_%: 5; Power_W: 0.063; Value2: 0.063W; VDC_V: 50; TempCo: 200 ppm/C; EIA_Code: E24; U/M: EA; AEC Category: Q200
R125 = CRCW040220K0FKED: RES, 20.0 k, 1%, 0.063 W, 0402; Manufacturer: Vishay-Dale; CompType: Resistor; Value: 20.0k; Res_ohm: 20000; Value_Code: 20k0; Tolerance_%: 1; Power_W: 0.063; Value2: 0.063W; VDC_V: 50; TempCo: 100 ppm/C; EIA_Code: E96; U/M: EA; AEC Category: Q200
U5 = LM5018MRX/NOPB: 100V, 300mA Constant On-Time Synchronous Buck Regulator, DDA0008B; Alternate PartNumber: LM5018MR/NOPB; Manufacturer: Texas Instruments; SymbolCreator: a0412235; CompType: IC; U/M: EA
U7 = LM317LIPK: 3-Terminal Adjustable Regulator, PK0003A; Manufacturer: Texas Instruments; SymbolCreater: a0411947; CompType: IC; U/M: EA

## Sheet Full Bridge.SchDoc
size 431 x 279 mm; Date: Not shown in title block; ApprovedBy: Not shown in title block; CheckedBy: Not shown in title block; Author: Not shown in title block; CompanyName: Not shown in title block; Engineer: Not shown in title block; Organization: Not shown in title block; Address1: Not shown in title block; Address2: Not shown in title block; Address3: Not shown in title block; Address4: Not shown in title block; DocumentNumber: 1; Revision: Use project parameter SCH_Rev; SheetNumber: 2; SheetTotal: 3
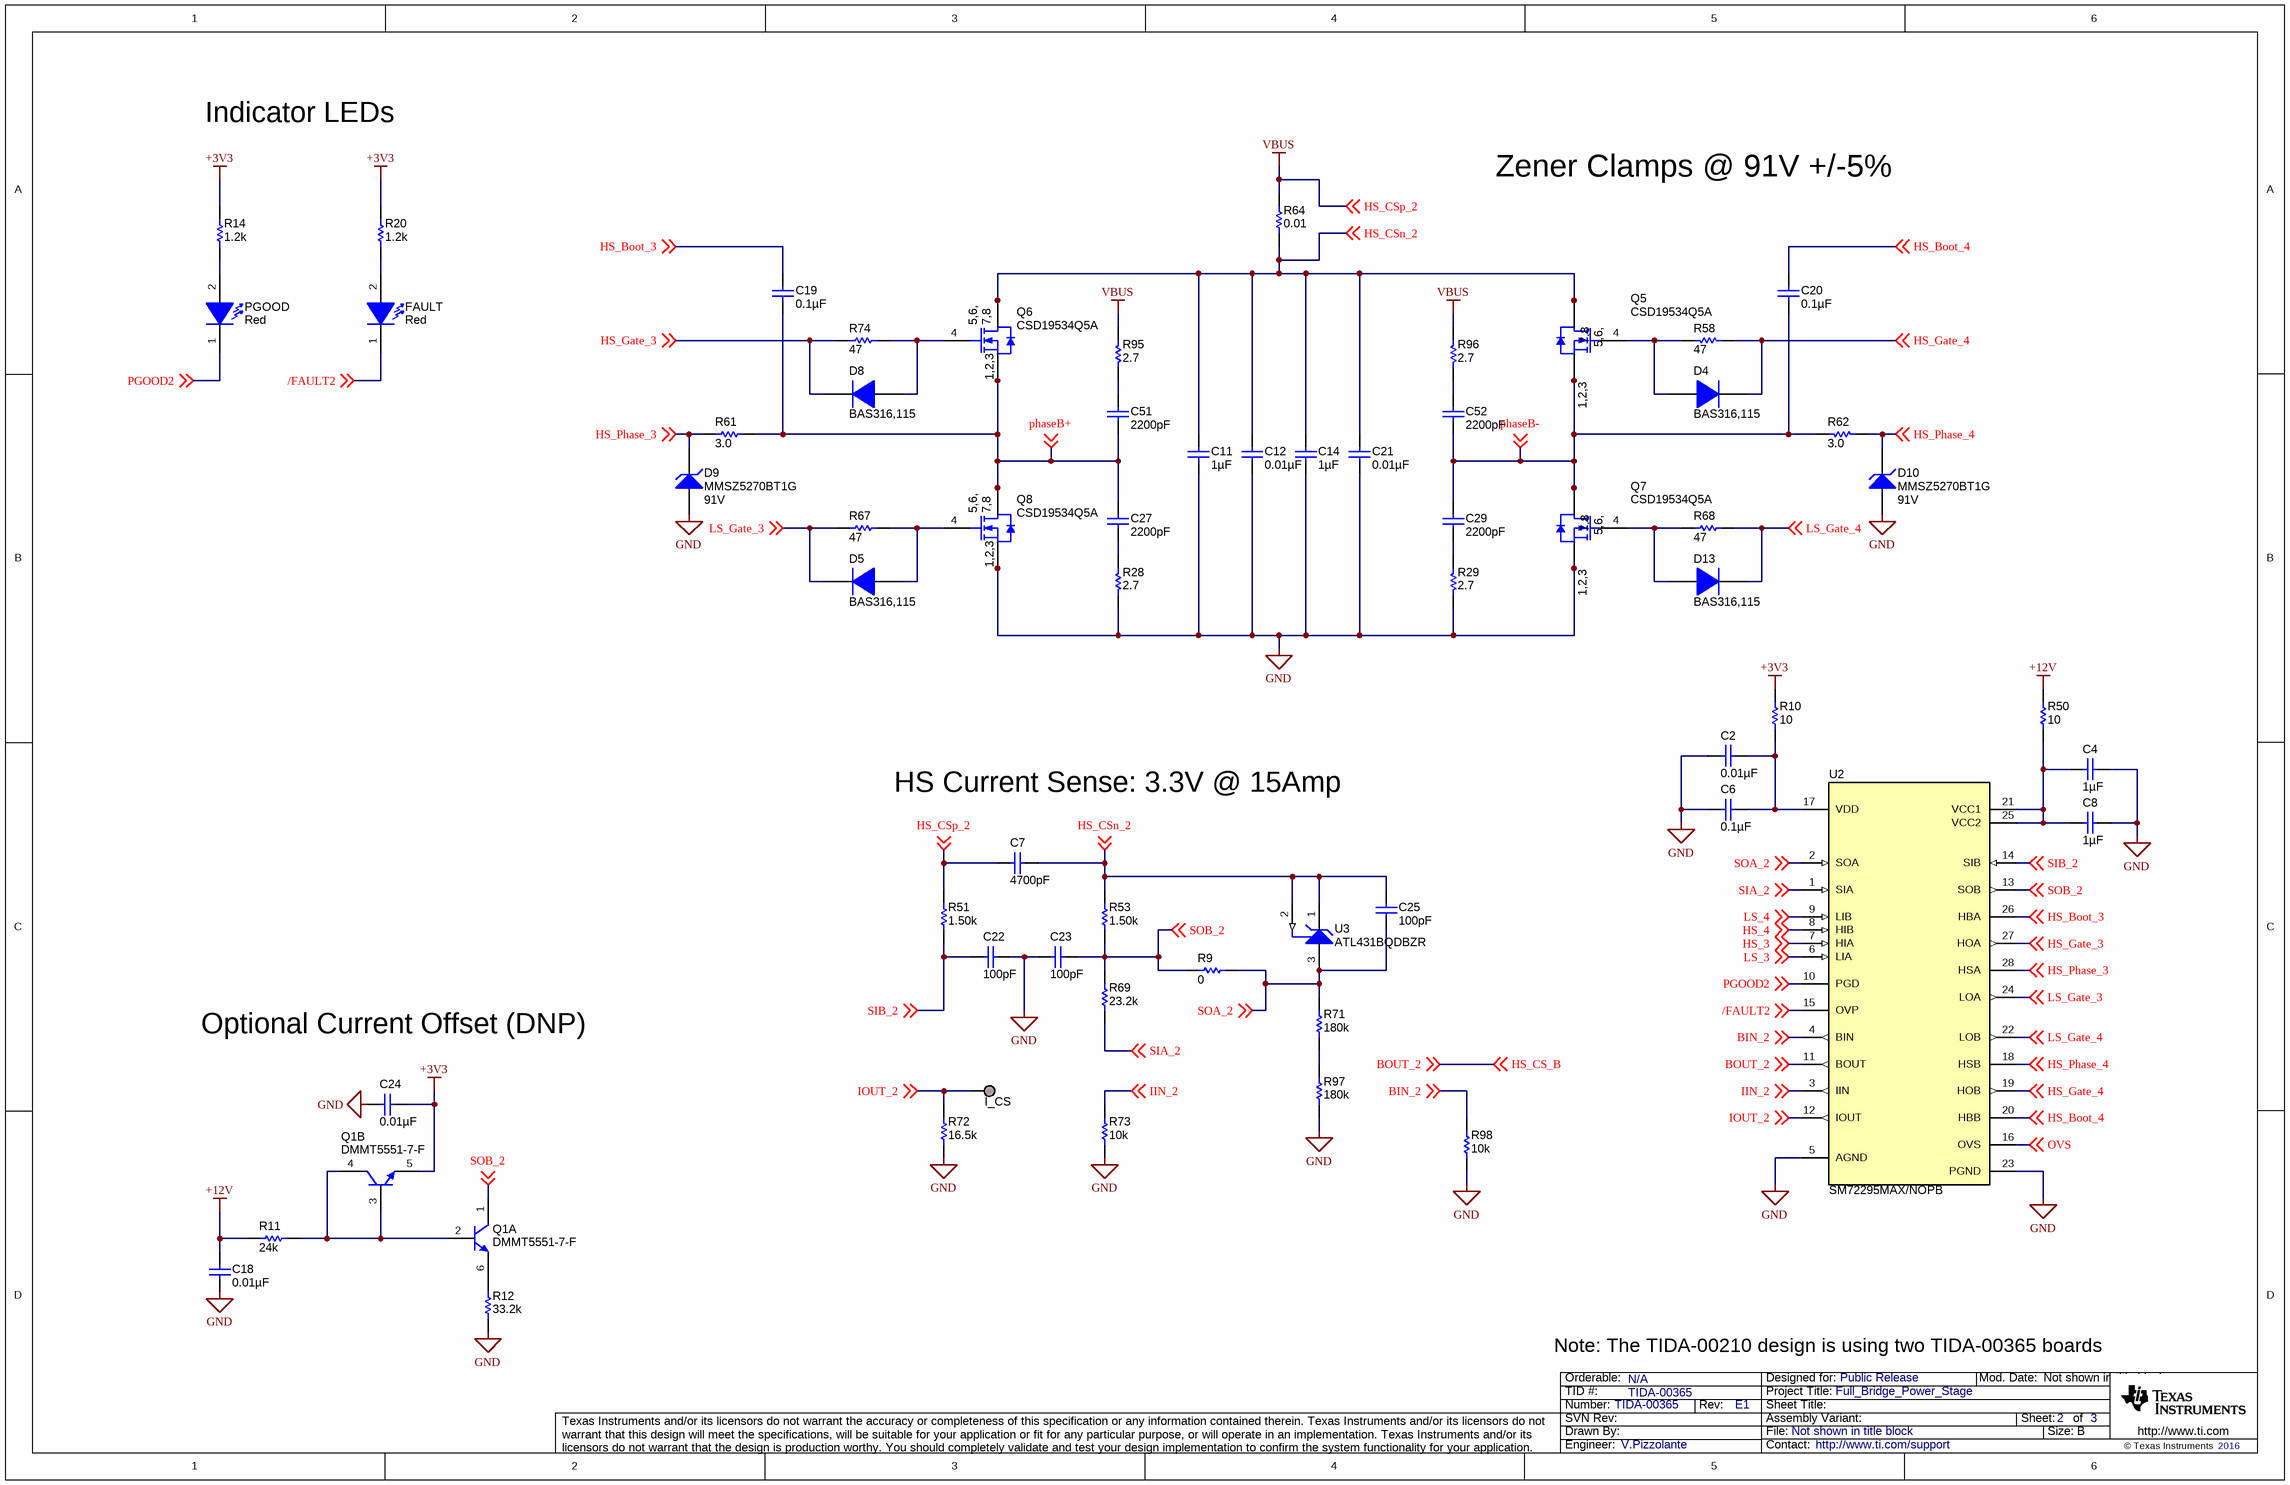
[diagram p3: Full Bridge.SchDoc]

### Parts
C2  ValueDisplayed: 0.01µF  [0402]  (hidden comment: 885012205031)
C4  ValueDisplayed: 1µF  [0603]  (hidden comment: 885012106017)
C6  ValueDisplayed: 0.1µF  [0402]  (hidden comment: C1005X7R1E104M050BB)
C7  ValueDisplayed: 4700pF  [0402]  (hidden comment: GRM155R72A472KA01D)
C8  ValueDisplayed: 1µF  [0603]  (hidden comment: 885012106017)
C11  ValueDisplayed: 1µF  [0805_HV]  (hidden comment: C2012X7S2A105K125AB)
C12  ValueDisplayed: 0.01µF  [0603]  (hidden comment: 06031C103KAT2A)
C14  ValueDisplayed: 1µF  [0805_HV]  (hidden comment: C2012X7S2A105K125AB)
C18  ValueDisplayed: 0.01µF  [0402]  (hidden comment: 885012205031)
C19  ValueDisplayed: 0.1µF  [0805_HV]  (hidden comment: C2012X7R2A104K125AA)
C20  ValueDisplayed: 0.1µF  [0805_HV]  (hidden comment: C2012X7R2A104K125AA)
C21  ValueDisplayed: 0.01µF  [0603]  (hidden comment: 06031C103KAT2A)
C22  ValueDisplayed: 100pF  [0402]  (hidden comment: 885012205055)
C23  ValueDisplayed: 100pF  [0402]  (hidden comment: 885012205055)
C24  ValueDisplayed: 0.01µF  [0402]  (hidden comment: 885012205031)
C25  ValueDisplayed: 100pF  [0402]  (hidden comment: 885012205055)
C27  ValueDisplayed: 2200pF  [0603]  (hidden comment: 06031C222JAT2A)
C29  ValueDisplayed: 2200pF  [0603]  (hidden comment: 06031C222JAT2A)
C51  ValueDisplayed: 2200pF  [0603]  (hidden comment: 06031C222JAT2A)
C52  ValueDisplayed: 2200pF  [0603]  (hidden comment: 06031C222JAT2A)
D4  BAS316,115  [sod-323]
D5  BAS316,115  [sod-323]
D8  BAS316,115  [sod-323]
D9  MMSZ5270BT1G  value 91V  [SOD-123]
D10  MMSZ5270BT1G  value 91V  [SOD-123]
D13  BAS316,115  [sod-323]
FAULT  value Red  [WL-SMCW_RED]  (hidden comment: 150060RS75000)
I_CS  TESTPOINT  [TP_SM_1MM]  (value not drawn)  (no BOM)
PGOOD  value Red  [WL-SMCW_RED]  (hidden comment: 150060RS75000)
Q1  DMMT5551-7-F  [SOT-26]  (parts A,B of 2)
Q5  CSD19534Q5A  [TRANS_NexFET_Q5A]
Q6  CSD19534Q5A  [TRANS_NexFET_Q5A]
Q7  CSD19534Q5A  [TRANS_NexFET_Q5A]
Q8  CSD19534Q5A  [TRANS_NexFET_Q5A]
R9  ValueDisplayed: 0  [0402]  (hidden comment: CRCW04020000Z0ED)
R10  ValueDisplayed: 10  [0603]  (hidden comment: CRCW060310R0JNEA)
R11  ValueDisplayed: 24k  [0402]  (hidden comment: CRCW040224K0JNED)
R12  ValueDisplayed: 33.2k  [0402]  (hidden comment: CRCW040233K2FKED)
R14  ValueDisplayed: 1.2k  [0402]  (hidden comment: CRCW04021K20JNED)
R20  ValueDisplayed: 1.2k  [0402]  (hidden comment: CRCW04021K20JNED)
R28  ValueDisplayed: 2.7  [0805_HV]  (hidden comment: CRCW08052R70JNEA)
R29  ValueDisplayed: 2.7  [0805_HV]  (hidden comment: CRCW08052R70JNEA)
R50  ValueDisplayed: 10  [0603]  (hidden comment: CRCW060310R0JNEA)
R51  ValueDisplayed: 1.50k  [0402]  (hidden comment: CRCW04021K50FKED)
R53  ValueDisplayed: 1.50k  [0402]  (hidden comment: CRCW04021K50FKED)
R58  ValueDisplayed: 47  [0603]  (hidden comment: CRCW060347R0JNEA)
R61  ValueDisplayed: 3.0  [0603]  (hidden comment: CRCW06033R00JNEA)
R62  ValueDisplayed: 3.0  [0603]  (hidden comment: CRCW06033R00JNEA)
R64  ValueDisplayed: 0.01  [2512]  (hidden comment: CRA2512-FZ-R010ELF)
R67  ValueDisplayed: 47  [0603]  (hidden comment: CRCW060347R0JNEA)
R68  ValueDisplayed: 47  [0603]  (hidden comment: CRCW060347R0JNEA)
R69  ValueDisplayed: 23.2k  [0402]  (hidden comment: CRCW040223K2FKED)
R71  ValueDisplayed: 180k  [0402]  (hidden comment: CRCW0402180KJNED)
R72  ValueDisplayed: 16.5k  [0402]  (hidden comment: CRCW040216K5FKED)
R73  ValueDisplayed: 10k  [0402]  (hidden comment: CRCW040210K0JNED)
R74  ValueDisplayed: 47  [0603]  (hidden comment: CRCW060347R0JNEA)
R95  ValueDisplayed: 2.7  [0805_HV]  (hidden comment: CRCW08052R70JNEA)
R96  ValueDisplayed: 2.7  [0805_HV]  (hidden comment: CRCW08052R70JNEA)
R97  ValueDisplayed: 180k  [0402]  (hidden comment: CRCW0402180KJNED)
R98  ValueDisplayed: 10k  [0402]  (hidden comment: CRCW040210K0JNED)
U2  SM72295MAX/NOPB  [DW0028A_N]
U3  ATL431BQDBZR  [DBZ0003A_N]

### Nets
+3V3: C24.1 Q1.5(E) R10.2 R14.2 R20.2
+12V: C18.1 R11.2 R50.2
GND: C2.2 C4.1 C6.2 C8.1 C11.2 C12.2 C14.2 C18.2 C21.2 C22.1 C23.2 C24.2 D9.2(A) D10.2(A) Q7.1(S) Q7.2(S) Q7.3(S) Q8.1(S) Q8.2(S) Q8.3(S) R12.1 R28.2 R29.2 R72.1 R73.1 R97.1 R98.1 U2.5(AGND) U2.23(PGND)
VBUS: C7.1 R51.2 R64.2 R95.2 R96.2 ; off-sheet HS_CSp_2  [also labelled HS_CSp_2]
/FAULT2: FAULT.1(K) U2.15(OVP) ; off-sheet /FAULT2
BIN_2: R98.2 U2.4(BIN) ; off-sheet BIN_2
BOUT_2: U2.11(BOUT) ; off-sheet BOUT_2, off-sheet HS_CS_B  [also labelled HS_CS_B]
HS_3: U2.7(HIA) ; off-sheet HS_3
HS_4: U2.8(HIB) ; off-sheet HS_4
HS_Boot_3: C19.1 U2.26(HBA) ; off-sheet HS_Boot_3
HS_Boot_4: C20.1 U2.20(HBB) ; off-sheet HS_Boot_4
HS_CSn_2: C7.2 C11.1 C12.1 C14.1 C21.1 C25.1 Q5.5(D) Q5.6(D) Q5.7(D) Q5.8(D) Q5.9(D) Q6.5(D) Q6.6(D) Q6.7(D) Q6.8(D) Q6.9(D) R53.2 R64.1 U3.1(CATHODE) U3.2(REF) ; off-sheet HS_CSn_2
HS_Gate_3: D8.1(K) R74.1 U2.27(HOA) ; off-sheet HS_Gate_3
HS_Gate_4: D4.1(K) R58.1 U2.19(HOB) ; off-sheet HS_Gate_4
HS_Phase_3: D9.1(K) R61.1 U2.28(HSA) ; off-sheet HS_Phase_3
HS_Phase_4: D10.1(K) R62.1 U2.18(HSB) ; off-sheet HS_Phase_4
IIN_2: R73.2 U2.3(IIN) ; off-sheet IIN_2
IOUT_2: I_CS.1 R72.2 U2.12(IOUT) ; off-sheet IOUT_2
LS_3: U2.6(LIA) ; off-sheet LS_3
LS_4: U2.9(LIB) ; off-sheet LS_4
LS_Gate_3: D5.1(K) R67.1 U2.24(LOA) ; off-sheet LS_Gate_3
LS_Gate_4: D13.1(K) R68.2 U2.22(LOB) ; off-sheet LS_Gate_4
OVS: U2.16(OVS) ; off-sheet OVS
PGOOD2: PGOOD.1(K) U2.10(PGD) ; off-sheet PGOOD2
phaseB+: C19.2 C27.2 C51.2 Q6.1(S) Q6.2(S) Q6.3(S) Q8.5(D) Q8.6(D) Q8.7(D) Q8.8(D) Q8.9(D) R61.2 ; off-sheet phaseB+
phaseB-: C20.2 C29.2 C52.2 Q5.1(S) Q5.2(S) Q5.3(S) Q7.5(D) Q7.6(D) Q7.7(D) Q7.8(D) Q7.9(D) R62.2 ; off-sheet phaseB-
SIA_2: R69.1 U2.1(SIA) ; off-sheet SIA_2
SIB_2: C22.2 R51.1 U2.14(SIB) ; off-sheet SIB_2
SOA_2: C25.2 R9.1 R71.1 U2.2(SOA) U3.3(ANODE) ; off-sheet SOA_2
SOB_2: C23.1 Q1.1(C) R9.2 R53.1 R69.2 U2.13(SOB) ; off-sheet SOB_2
NetC2_1: C2.1 C6.1 R10.1 U2.17(VDD)
NetC4_2: C4.2 C8.2 R50.1 U2.21(VCC1) U2.25(VCC2)
NetC27_1: C27.1 R28.1
NetC29_1: C29.1 R29.1
NetC51_1: C51.1 R95.1
NetC52_1: C52.1 R96.1
NetD4_2: D4.2(A) Q5.4(G) R58.2
NetD5_2: D5.2(A) Q8.4(G) R67.2
NetD8_2: D8.2(A) Q6.4(G) R74.2
NetD13_2: D13.2(A) Q7.4(G) R68.1
NetFAULT_2: FAULT.2(A) R20.1
NetPGOOD_2: PGOOD.2(A) R14.1
NetQ1_2: Q1.2(B) Q1.3(B) Q1.4(C) R11.1
NetQ1_6: Q1.6(E) R12.2
NetR71_2: R71.2 R97.2

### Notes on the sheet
- Indicator LEDs
- Zener Clamps @ 91V +/-5%
- HS Current Sense: 3.3V @ 15Amp
- Optional Current Offset (DNP)
- Note: The TIDA-00210 design is using two TIDA-00365 boards

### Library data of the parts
C2 C18 C24 = 885012205031: as C9 on sheet Protections
C4 C8 = 885012106017: CAP, CERM, 1 µF, 16 V, +/- 20%, X5R, 0603; Manufacturer: Wurth Elektronik; Polarized: N; CompType: Capacitor; Value: 1uF; U/M: EA; Cap_F: 0.000001; Tolerance_%: 20; Value1: Unknown; VDC_V: 16; Value2: 16V; TaMin_C: -55; TaMax_C: 85; AEC Category: Q200
C6 = C1005X7R1E104M050BB: as C1 on sheet Protections
C7 = GRM155R72A472KA01D: CAP, CERM, 4700 pF, 100 V, +/- 10%, X7R, 0402; Manufacturer: MuRata; Polarized: N; CompType: Capacitor; Value: 4700pF; U/M: EA; Cap_F: 0.0000000047; Tolerance_%: 10; Value1: Unknown; VDC_V: 100; Value2: 100V; TaMin_C: -55; TaMax_C: 125; AEC Category: Q200
C11 C14 = C2012X7S2A105K125AB: CAP, CERM, 1 µF, 100 V, +/- 10%, X7S, 0805; Manufacturer: TDK; Polarized: N; CompType: Capacitor; Value: 1uF; U/M: EA; Cap_F: 0.000001; Tolerance_%: 10; Value1: Unknown; VDC_V: 100; Value2: 100V; TaMin_C: -55; TaMax_C: 125; Cap_Case: 0805; AEC Category: Q200
C12 C21 = 06031C103KAT2A: CAP, CERM, 0.01 µF, 100 V, +/- 10%, X7R, 0603; Manufacturer: AVX; Polarized: N; CompType: Capacitor; Value: 0.01uF; U/M: EA; Cap_F: 0.00000001; Tolerance_%: 10; ESR_ohm: 0.098; Value1: 0.098 ohm; VDC_V: 100; Value2: 100V; TaMin_C: -55; TaMax_C: 125; AEC Category: Q200
C19 C20 = C2012X7R2A104K125AA: CAP, CERM, 0.1 µF, 100 V, +/- 10%, X7R, 0805; Manufacturer: TDK; Polarized: N; CompType: Capacitor; Value: 0.1uF; U/M: EA; Cap_F: 0.0000001; Tolerance_%: 10; ESR_ohm: 0.0158; Value1: 0.0158 ohm; VDC_V: 100; Value2: 100V; TaMin_C: -55; TaMax_C: 125; Cap_Case: 0805; AEC Category: Q200
C22 C23 C25 = 885012205055: CAP, CERM, 100 pF, 50 V, +/- 10%, X7R, 0402; Manufacturer: Wurth Elektronik; Polarized: N; CompType: Capacitor; Value: 100pF; U/M: EA; Cap_F: 0.0000000001; Tolerance_%: 10; Value1: Unknown; VDC_V: 50; Value2: 50V; TaMin_C: -55; TaMax_C: 125; AEC Category: Q200
C27 C29 C51 C52 = 06031C222JAT2A: CAP, CERM, 2200 pF, 100 V, +/- 5%, X7R, 0603; Manufacturer: AVX; Polarized: N; CompType: Capacitor; Value: 2200pF; U/M: EA; Cap_F: 0.0000000022; Tolerance_%: 5; ESR_ohm: 0.192; Value1: 0.192 ohm; VDC_V: 100; Value2: 100V; TaMin_C: -55; TaMax_C: 125; AEC Category: Q200
D4 D5 D8 D13 = BAS316,115: as D3 on sheet Power Supply
D9 D10 = MMSZ5270BT1G: Diode, Zener, 91 V, 500 mW, SOD-123; Manufacturer: ON Semiconductor; SymbolCreator: a0412235; U/M: EA; Power_W: 0.5; Vz_V: 91; Value1: 0.5W; RJA_CperW: 340; AEC Category: Q101
FAULT PGOOD = 150060RS75000: as TRIP on sheet Protections
I_CS = TP_SM_1MM: 1mm Test Point, SMT; Manufacturer: Any
Q1 = DMMT5551-7-F, Diodes Inc.: Transistor, Dual NPN, 160 V, 0.2 A, SOT-26; SymbolCreator: Altium; PNP: 0; NPN: 2; Vceo_V: 160; Vcesat1_V: 0.15; Value: 160 V; IcRated_A: 0.2; Value1: 0.2 A; HfeMax: 250; TaMin_C: -55; TaMax_C: 150; CompType: BJT; U/M: EA; AEC Category: Q101; AEC Qualified: N
Q5-Q8 = CSD19534Q5A: MOSFET, N-CH, 100 V, 10 A, SON 5x6mm; Manufacturer: Texas Instruments; Alternate Manufacturer: None; U/M: EA; ChType: N; Value: 100V; VdsMax_V: 100; Value1: ? ohm; Value2: 17 nC; QgTyp_nC: 17; Vgs_V: 20; IdsMax_A: 10; AEC Category: Q101
R9 = CRCW04020000Z0ED: RES, 0, 5%, 0.063 W, 0402; Manufacturer: Vishay-Dale; CompType: Resistor; Value: 0; Value_Code: 0000; Tolerance_%: 5; Power_W: 0.063; Value2: 0.063W; VDC_V: 50; TempCo: 200 ppm/C; EIA_Code: E24; U/M: EA; AEC Category: Q200
R10 R50 = CRCW060310R0JNEA: as R78 on sheet Power Supply
R11 = CRCW040224K0JNED: RES, 24 k, 5%, 0.063 W, 0402; Manufacturer: Vishay-Dale; CompType: Resistor; Value: 24k; Res_ohm: 24000; Value_Code: 24k0; Tolerance_%: 5; Power_W: 0.063; Value2: 0.063W; VDC_V: 50; TempCo: 200 ppm/C; EIA_Code: E24; U/M: EA; AEC Category: Q200
R12 = CRCW040233K2FKED: RES, 33.2 k, 1%, 0.063 W, 0402; Manufacturer: Vishay-Dale; CompType: Resistor; Value: 33.2k; Res_ohm: 33200; Value_Code: 33k2; Tolerance_%: 1; Power_W: 0.063; Value2: 0.063W; VDC_V: 50; TempCo: 100 ppm/C; EIA_Code: E96; U/M: EA; AEC Category: Q200
R14 R20 = CRCW04021K20JNED: as R13 on sheet Protections
R28 R29 R95 R96 = CRCW08052R70JNEA: RES, 2.7, 5%, 0.125 W, 0805; Manufacturer: Vishay-Dale; CompType: Resistor; Value: 2.7; Value_Code: 2R70; Tolerance_%: 5; Power_W: 0.125; Value2: 0.125W; VDC_V: 150; TempCo: 200 ppm/C; EIA_Code: E24; U/M: EA; AEC Category: Q200
R51 R53 = CRCW04021K50FKED: RES, 1.50 k, 1%, 0.063 W, 0402; Manufacturer: Vishay-Dale; CompType: Resistor; Value: 1.50k; Res_ohm: 1500; Value_Code: 1k50; Tolerance_%: 1; Power_W: 0.063; Value2: 0.063W; VDC_V: 50; TempCo: 100 ppm/C; EIA_Code: E96; U/M: EA; AEC Category: Q200
R58 R67 R68 R74 = CRCW060347R0JNEA: RES, 47, 5%, 0.1 W, 0603; Manufacturer: Vishay-Dale; CompType: Resistor; Value: 47; Value_Code: 47R0; Tolerance_%: 5; Power_W: 0.1; Value2: 0.1W; VDC_V: 75; TempCo: 200 ppm/C; EIA_Code: E24; U/M: EA; AEC Category: Q200
R61 R62 = CRCW06033R00JNEA: RES, 3.0, 5%, 0.1 W, 0603; Manufacturer: Vishay-Dale; CompType: Resistor; Value: 3.0; Res_ohm: 3; Value_Code: 3R00; Tolerance_%: 5; Power_W: 0.1; Value2: 0.1W; VDC_V: 75; TempCo: 200 ppm/C; EIA_Code: E24; U/M: EA; AEC Category: Q200
R64 = CRA2512-FZ-R010ELF: RES, 0.01, 1%, 3 W, 2512; Manufacturer: Bourns; CompType: Resistor; Value: 0.01; Value_Code: R010; Tolerance_%: 1; Power_W: 3; Value2: 3W; TempCo: 75 ppm/C; EIA_Code: E96; U/M: EA; AEC Category: Q200
R69 = CRCW040223K2FKED: RES, 23.2 k, 1%, 0.063 W, 0402; Manufacturer: Vishay-Dale; CompType: Resistor; Value: 23.2k; Res_ohm: 23200; Value_Code: 23k2; Tolerance_%: 1; Power_W: 0.063; Value2: 0.063W; VDC_V: 50; TempCo: 100 ppm/C; EIA_Code: E96; U/M: EA; AEC Category: Q200
R71 R97 = CRCW0402180KJNED: RES, 180 k, 5%, 0.063 W, 0402; Manufacturer: Vishay-Dale; CompType: Resistor; Value: 180k; Res_ohm: 180000; Tolerance_%: 5; Power_W: 0.063; Value2: 0.063W; VDC_V: 50; TempCo: 200 ppm/C; EIA_Code: E24; U/M: EA; AEC Category: Q200
R72 = CRCW040216K5FKED: RES, 16.5 k, 1%, 0.063 W, 0402; Manufacturer: Vishay-Dale; CompType: Resistor; Value: 16.5k; Res_ohm: 16500; Value_Code: 16k5; Tolerance_%: 1; Power_W: 0.063; Value2: 0.063W; VDC_V: 50; TempCo: 100 ppm/C; EIA_Code: E96; U/M: EA; AEC Category: Q200
R73 R98 = CRCW040210K0JNED: RES, 10 k, 5%, 0.063 W, 0402; Manufacturer: Vishay-Dale; CompType: Resistor; Value: 10k; Res_ohm: 10000; Value_Code: 10k0; Tolerance_%: 5; Power_W: 0.063; Value2: 0.063W; VDC_V: 50; TempCo: 200 ppm/C; EIA_Code: E24; U/M: EA; AEC Category: Q200
U2 = SM72295MAX/NOPB: Photovoltaic Full Bridge Driver, DW0028A; Alternate PartNumber: SM72295MAE/NOPB; Manufacturer: Texas Instruments; SymbolCreator: a0411947; CompType: IC; U/M: EA
U3 = ATL431BQDBZR: 2.5V Low Iq Adjustable Precision Shunt Regulator, DBZ0003A; Alternate PartNumber: ATL431BQDBZT; Manufacturer: Texas Instruments; SymbolCreator: a0412235; CompType: IC; U/M: EA

## Sheet Interfaces.SchDoc
size 431 x 279 mm; Date: Not shown in title block; ApprovedBy: Not shown in title block; CheckedBy: Not shown in title block; Author: Not shown in title block; CompanyName: Not shown in title block; Engineer: Not shown in title block; Organization: Not shown in title block; Address1: Not shown in title block; Address2: Not shown in title block; Address3: Not shown in title block; Address4: Not shown in title block; DocumentNumber: 1; Revision: Use project parameter SCH_Rev; SheetNumber: 2; SheetTotal: 3
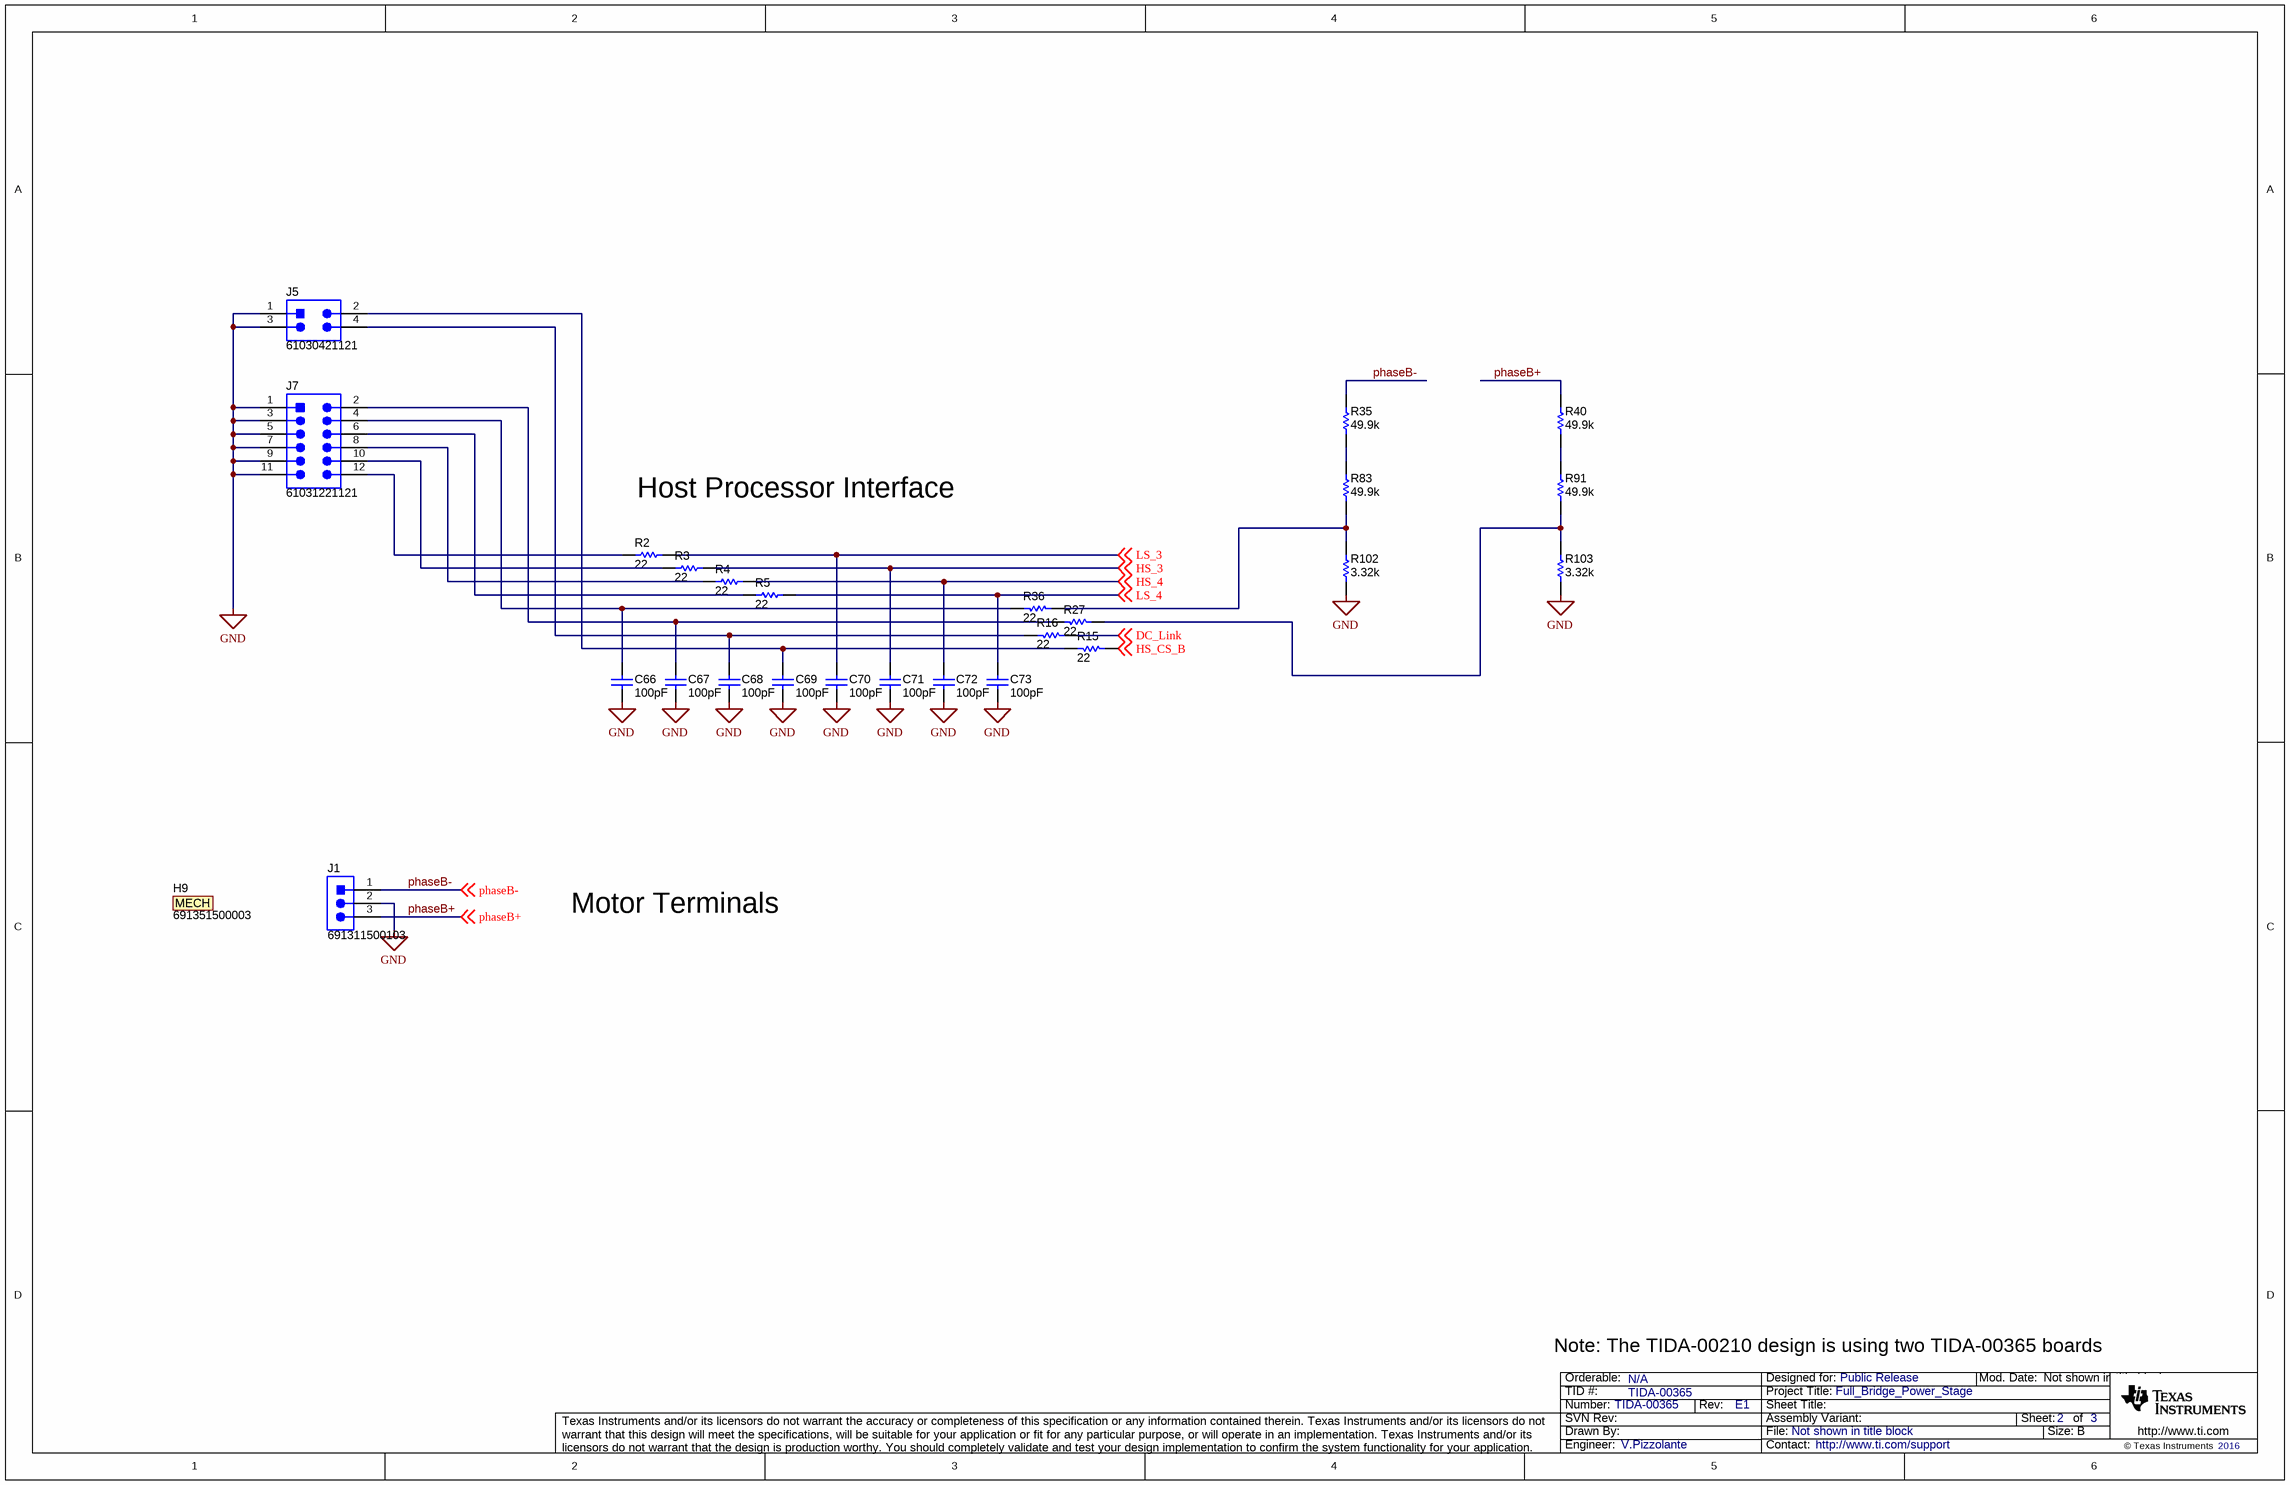
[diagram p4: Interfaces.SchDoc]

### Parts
C66  ValueDisplayed: 100pF  [0402]  (hidden comment: CC0402KRX7R9BB101)
C67  ValueDisplayed: 100pF  [0402]  (hidden comment: CC0402KRX7R9BB101)
C68  ValueDisplayed: 100pF  [0402]  (hidden comment: CC0402KRX7R9BB101)
C69  ValueDisplayed: 100pF  [0402]  (hidden comment: CC0402KRX7R9BB101)
C70  ValueDisplayed: 100pF  [0402]  (hidden comment: CC0402KRX7R9BB101)
C71  ValueDisplayed: 100pF  [0402]  (hidden comment: CC0402KRX7R9BB101)
C72  ValueDisplayed: 100pF  [0402]  (hidden comment: CC0402KRX7R9BB101)
C73  ValueDisplayed: 100pF  [0402]  (hidden comment: CC0402KRX7R9BB101)
H9  691351500003  (mechanical)
J1  691311500103  [Wurth_691311500103]
J5  61030421121  [Wurth_61030421121]
J7  61031221121  [Wurth_61031221121]
R2  ValueDisplayed: 22  [0402]  (hidden comment: CRCW040222R0JNED)
R3  ValueDisplayed: 22  [0402]  (hidden comment: CRCW040222R0JNED)
R4  ValueDisplayed: 22  [0402]  (hidden comment: CRCW040222R0JNED)
R5  ValueDisplayed: 22  [0402]  (hidden comment: CRCW040222R0JNED)
R15  ValueDisplayed: 22  [0402]  (hidden comment: CRCW040222R0JNED)
R16  ValueDisplayed: 22  [0402]  (hidden comment: CRCW040222R0JNED)
R27  ValueDisplayed: 22  [0402]  (hidden comment: CRCW040222R0JNED)
R35  ValueDisplayed: 49.9k  [0402]  (hidden comment: CRCW040249K9FKED)
R36  ValueDisplayed: 22  [0402]  (hidden comment: CRCW040222R0JNED)
R40  ValueDisplayed: 49.9k  [0402]  (hidden comment: CRCW040249K9FKED)
R83  ValueDisplayed: 49.9k  [0402]  (hidden comment: CRCW040249K9FKED)
R91  ValueDisplayed: 49.9k  [0402]  (hidden comment: CRCW040249K9FKED)
R102  ValueDisplayed: 3.32k  [0402]  (hidden comment: CRCW04023K32FKED)
R103  ValueDisplayed: 3.32k  [0402]  (hidden comment: CRCW04023K32FKED)

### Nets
GND: C66.1 C67.1 C68.1 C69.1 C70.2 C71.2 C72.2 C73.2 J1.2 J5.1 J5.3 J7.1 J7.3 J7.5 J7.7 J7.9 J7.11 R102.1 R103.1
DC_Link: R16.2 ; off-sheet DC_Link
HS_3: C71.1 R3.2 ; off-sheet HS_3
HS_4: C72.1 R4.2 ; off-sheet HS_4
HS_CS_B: R15.2 ; off-sheet HS_CS_B  [project net BOUT_2]
LS_3: C70.1 R2.2 ; off-sheet LS_3
LS_4: C73.1 R5.2 ; off-sheet LS_4
phaseB+: J1.3 R40.2 ; off-sheet phaseB+
phaseB-: J1.1 R35.2 ; off-sheet phaseB-
NetC66_2: C66.2 J7.4 R36.1
NetC67_2: C67.2 J7.2 R27.1
NetC68_2: C68.2 J5.4 R16.1
NetC69_2: C69.2 J5.2 R15.1
NetJ7_6: J7.6 R5.1
NetJ7_8: J7.8 R4.1
NetJ7_10: J7.10 R3.1
NetJ7_12: J7.12 R2.1
NetR27_2: R27.2 R91.1 R103.2
NetR35_1: R35.1 R83.2
NetR36_2: R36.2 R83.1 R102.2
NetR40_1: R40.1 R91.2

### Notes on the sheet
- Host Processor Interface
- Motor Terminals
- Note: The TIDA-00210 design is using two TIDA-00365 boards

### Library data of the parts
C66-C73 = CC0402KRX7R9BB101: as C10 on sheet Protections
H9 = 691351500003: TERM BLOCK PLUG 3POS 5.08MM; Manufacturer: Wurth Elektronik; SymbolCreator: codlsc
J1 = 691311500103: Header (Shrouded), 5.08mm, 3x1, Tin, TH; Manufacturer: Wurth Elektronik; SymbolCreator: a0799628; Pitch_mm: 5.08; Gender: Male; Shrouded: Y; Row_Count: 1; Current_A: 20; Voltage_V: 300
J5 = 61030421121: as J2 on sheet Power Supply
J7 = 61031221121: Header, 2.54mm, 6x2, Gold, SMT; Manufacturer: Wurth Elektronik; SymbolCreator: a0412235; Pitch_mm: 2.54; Gender: Male; Shrouded: N; Row_Count: 2; Current_A: 3; Voltage_V: 250
R2-R5 R15 R16 R27 R36 = CRCW040222R0JNED: RES, 22, 5%, 0.063 W, 0402; Manufacturer: Vishay-Dale; CompType: Resistor; Value: 22; Value_Code: 22R0; Tolerance_%: 5; Power_W: 0.063; Value2: 0.063W; VDC_V: 50; TempCo: 200 ppm/C; EIA_Code: E24; U/M: EA; AEC Category: Q200
R35 R40 R83 R91 = CRCW040249K9FKED: as R21 on sheet Protections
R102 R103 = CRCW04023K32FKED: RES, 3.32 k, 1%, 0.063 W, 0402; Manufacturer: Vishay-Dale; CompType: Resistor; Value: 3.32k; Res_ohm: 3320; Value_Code: 3k32; Tolerance_%: 1; Power_W: 0.063; Value2: 0.063W; VDC_V: 50; TempCo: 100 ppm/C; EIA_Code: E96; U/M: EA; AEC Category: Q200

## Sheet TIDA00365_Screws.SchDoc
size 431 x 279 mm; Date: Not shown in title block; ApprovedBy: Not shown in title block; CheckedBy: Not shown in title block; Author: Not shown in title block; CompanyName: Not shown in title block; Engineer: Not shown in title block; Organization: Not shown in title block; Address1: Not shown in title block; Address2: Not shown in title block; Address3: Not shown in title block; Address4: Not shown in title block; DocumentNumber: 1; Revision: Use project parameter SCH_Rev; SheetNumber: 3; SheetTotal: 3; PageSetup: Record=PageOptions¦CenterHorizontal=True¦CenterVertical=True¦PrintScale=1.00¦XCorrection=1.00¦YCorrection=1.00¦PrintKind=0¦BorderSize=5000000¦LeftOffset=0¦BottomOffset=0¦Orientation=2¦PaperLength=1000¦PaperWidth=1000¦Scale=100¦PaperSource=15¦PrintQuality=600¦MediaType=1¦DitherType=10¦PaperKind=Letter¦PrintScaleMode=1
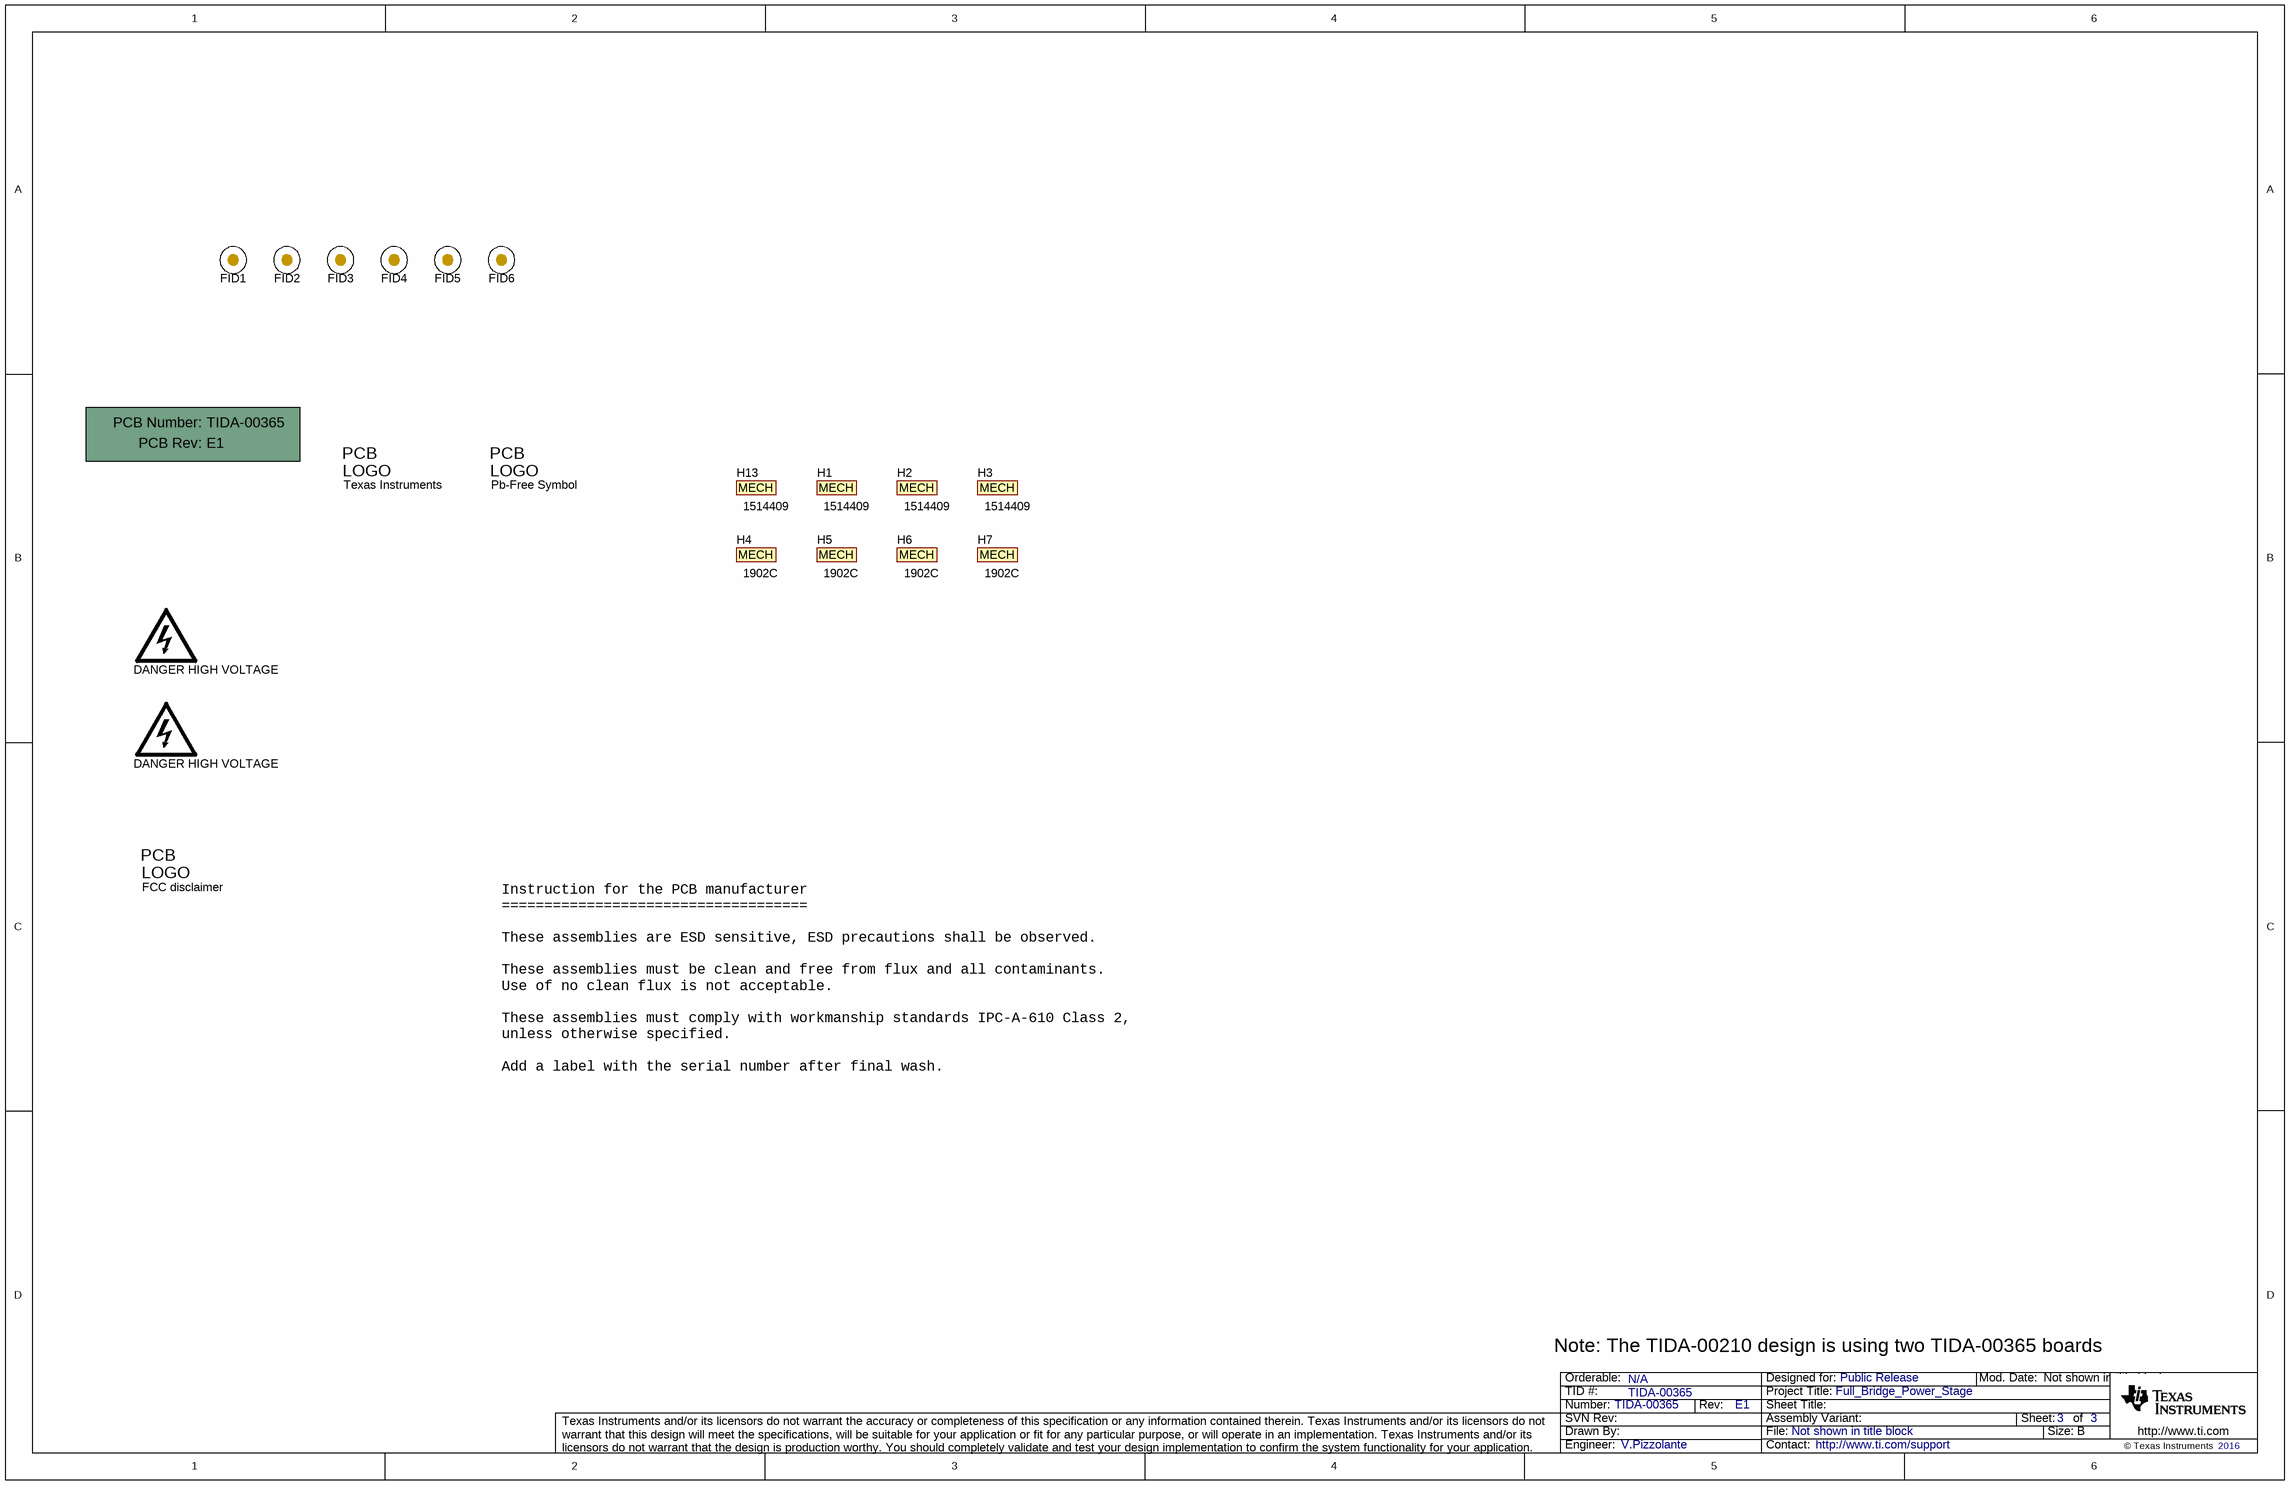
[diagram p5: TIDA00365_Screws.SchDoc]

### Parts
!PCB  Printed Circuit Board  (value not drawn)  (mechanical)
DANGER_HIGH_VOLTAGE  DANGER HIGH VOLTAGE  [IEC_HighVoltage_Small]  (no BOM)
DANGER_HIGH_VOLTAGE!  DANGER HIGH VOLTAGE  [IEC_HighVoltage_Small]  (no BOM)
FID1  Fiducial  [Fiducial6.4-20]  (value not drawn)
FID2  Fiducial  [Fiducial6.4-20]  (value not drawn)
FID3  Fiducial  [Fiducial6.4-20]  (value not drawn)
FID4  Fiducial  [Fiducial6.4-20]  (value not drawn)
FID5  Fiducial  [Fiducial6.4-20]  (value not drawn)
FID6  Fiducial  [Fiducial6.4-20]  (value not drawn)
H1  PartNumber: 1514409  (hidden comment: 149513 - Farnell)  (mechanical)
H2  PartNumber: 1514409  (hidden comment: 149513 - Farnell)  (mechanical)
H3  PartNumber: 1514409  (hidden comment: 149513 - Farnell)  (mechanical)
H4  PartNumber: 1902C  (hidden comment: 149513 - Farnell)  (mechanical)
H5  PartNumber: 1902C  (hidden comment: 149513 - Farnell)  (mechanical)
H6  PartNumber: 1902C  (hidden comment: 149513 - Farnell)  (mechanical)
H7  PartNumber: 1902C  (hidden comment: 149513 - Farnell)  (mechanical)
H13  PartNumber: 1514409  (hidden comment: 149513 - Farnell)  (mechanical)
Logo1  Texas Instruments  [TI_Stacked_Overlay_Small]  (no BOM)
Logo2  Pb-Free Symbol  [Pb-Free_Overlay_Small]  (no BOM)
Logo3  FCC disclaimer  [FCC_disclaimer]  (no BOM)

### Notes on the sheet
- Instruction for the PCB manufacturer
  ====================================
  These assemblies are ESD sensitive, ESD precautions shall be observed.
  These assemblies must be clean and free from flux and all contaminants.
  Use of no clean flux is not acceptable.
  These assemblies must comply with workmanship standards IPC-A-610 Class 2,
  unless otherwise specified.
  Add a label with the serial number after final wash.
- Note: The TIDA-00210 design is using two TIDA-00365 boards

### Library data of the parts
!PCB = PCB: Manufacturer: Any; PartNumber: TIDA-00365; SymbolCreator: a0412235
DANGER_HIGH_VOLTAGE DANGER_HIGH_VOLTAGE! = IEC_HighVoltage: IEC 61010-1 High Voltage Warning; SymbolCreator: a0412235
FID1-FID6 = Fiducial: Fiducial mark.  There is nothing to buy or mount.; SymbolCreator: codlsc
H1-H3 H13 = MechPart: Will add component to BOM.  Useful for cables, nuts, etc. not in libraries; SymbolCreator: codlsc; CompType: Mechanical; U/M: EA
H4-H7 = MechPart: Will add component to BOM.  Useful for cables, nuts, etc. not in libraries; Manufacturer: Standoff; SymbolCreator: codlsc; CompType: Mechanical; U/M: EA
Logo1 = TI_Logo: Texas Instrument Corporate Signature; SymbolCreator: codlsc
Logo2 = Pb-Free: SymbolCreator: a0412235
Logo3 = FCC_disclaimer: SymbolCreator: codlsc

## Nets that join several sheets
+3V3: Protections (C1.1 D1.2 U1.4), Power Supply (5 pins), Full Bridge (5 pins)
+12V: Protections (7 pins), Power Supply (8 pins), Full Bridge (C18.1 R11.2 R50.2)
GND: Protections (22 pins), Power Supply (22 pins), Full Bridge (29 pins), Interfaces (19 pins)
VBUS: Protections (R21.2), Power Supply (7 pins), Full Bridge (5 pins)
BOUT_2: Protections (R85.1), Full Bridge (U2.11), Interfaces (R15.2)
DC_Link: Protections (D1.3 R22.2 R81.1), Interfaces (R16.2)
HS_3: Full Bridge (U2.7), Interfaces (C71.1 R3.2)
HS_4: Full Bridge (U2.8), Interfaces (C72.1 R4.2)
LS_3: Full Bridge (U2.6), Interfaces (C70.1 R2.2)
LS_4: Full Bridge (U2.9), Interfaces (C73.1 R5.2)
OVS: Protections (R66.1 U9.4), Full Bridge (U2.16)
phaseB+: Full Bridge (12 pins), Interfaces (J1.3 R40.2)
phaseB-: Full Bridge (12 pins), Interfaces (J1.1 R35.2)

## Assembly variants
First Assembly: not fitted H18 Q1 R9 R11 R12
Production: not fitted C18 C24 Q1 R9 R11 R12 R25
